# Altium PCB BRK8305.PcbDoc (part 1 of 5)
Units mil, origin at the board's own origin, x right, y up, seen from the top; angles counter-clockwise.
Board outline 5944.89 x 4139.76 mil, 4 copper layers (L1-Top, L2-GND, L3-GND, L4-BOT), stack 61.2 mil thick; 237 components, 286 nets, 1257 pads, 698 vias.
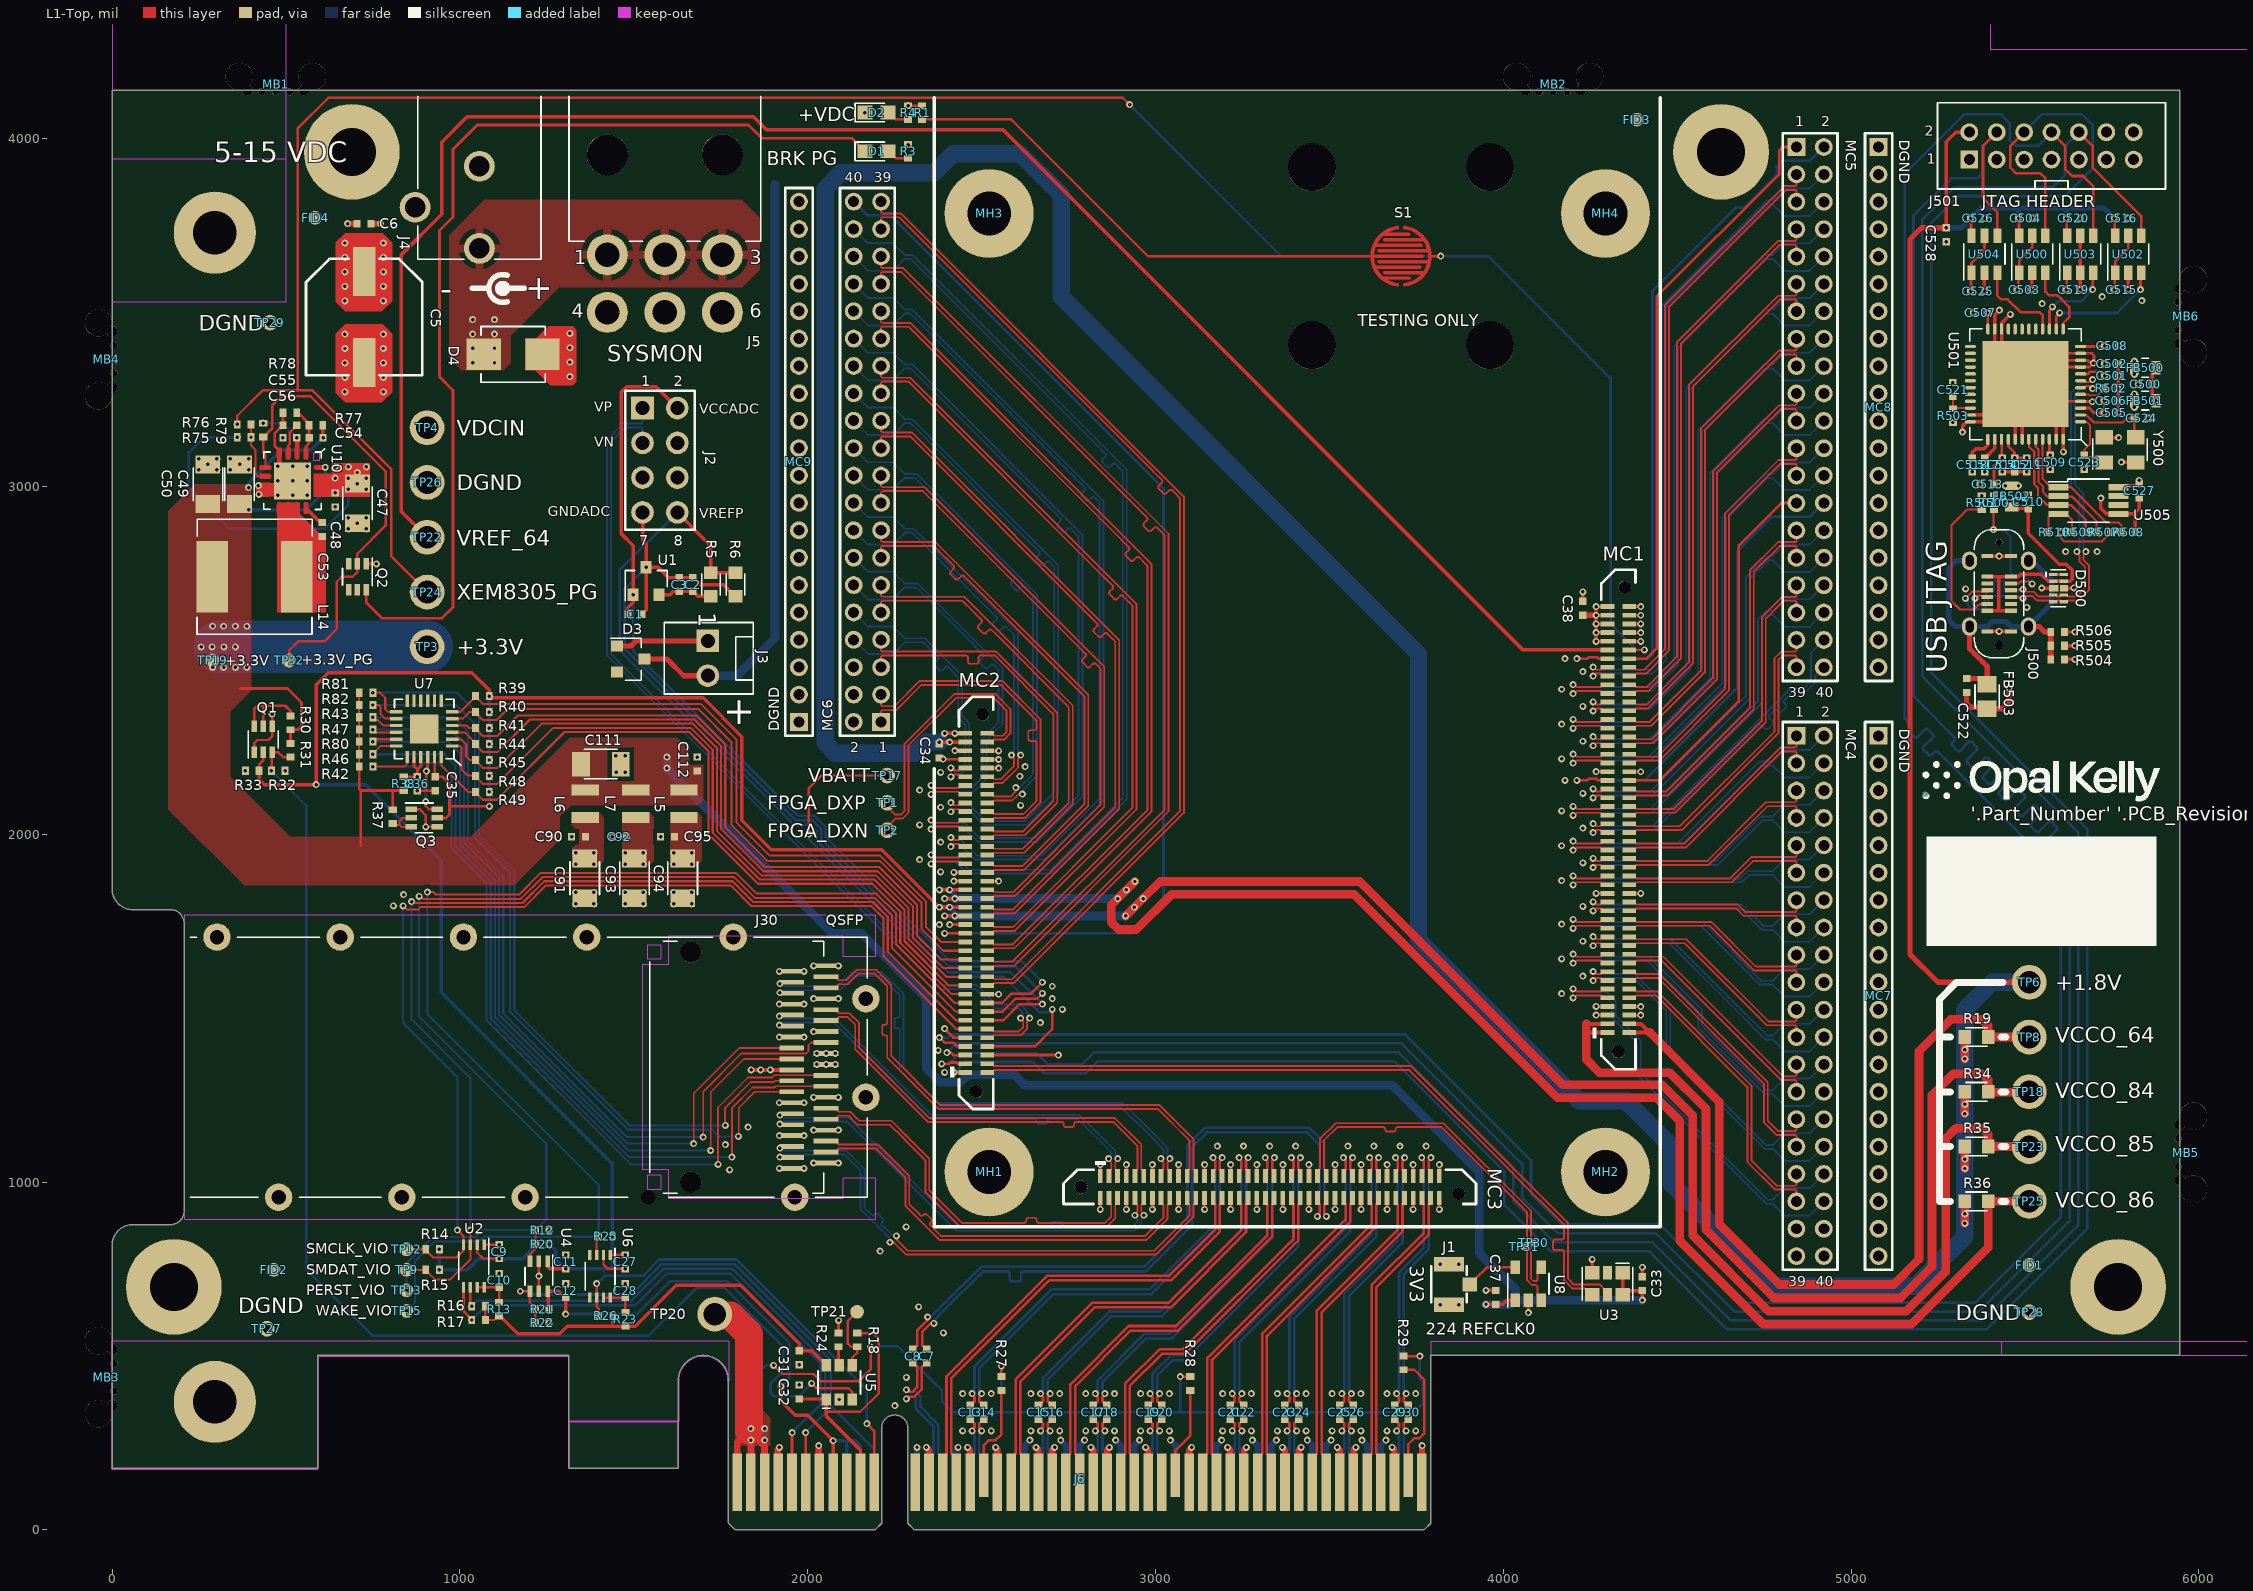
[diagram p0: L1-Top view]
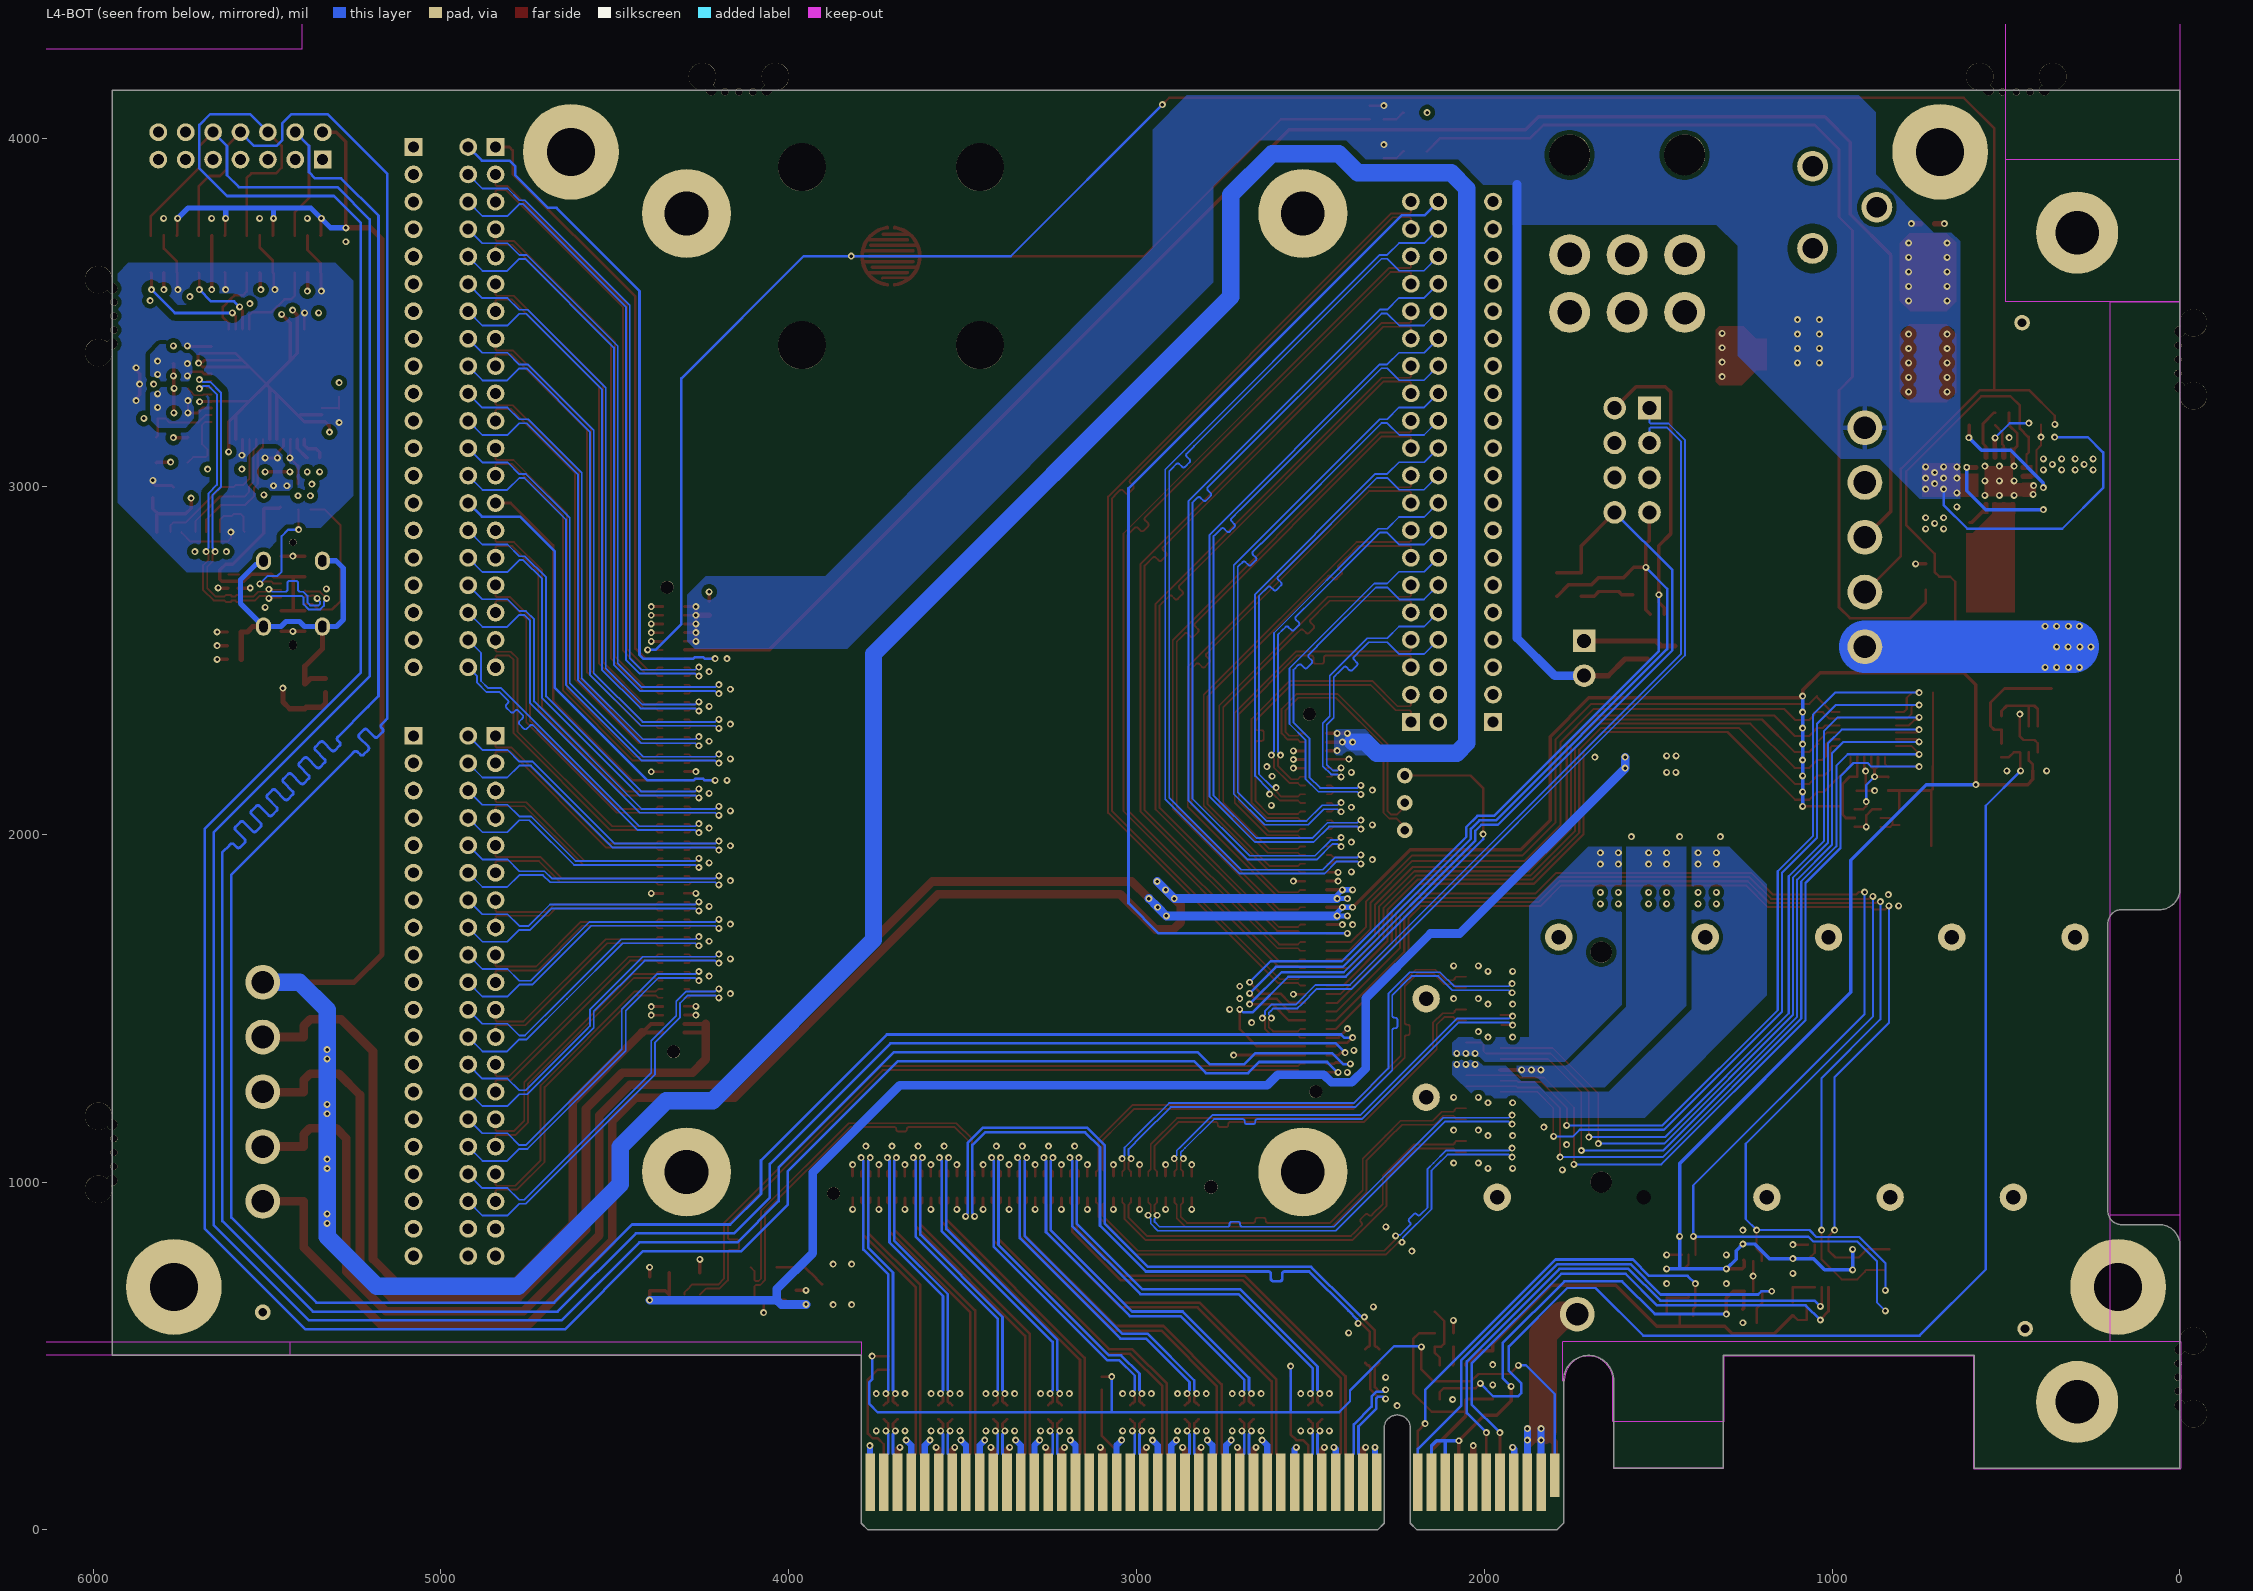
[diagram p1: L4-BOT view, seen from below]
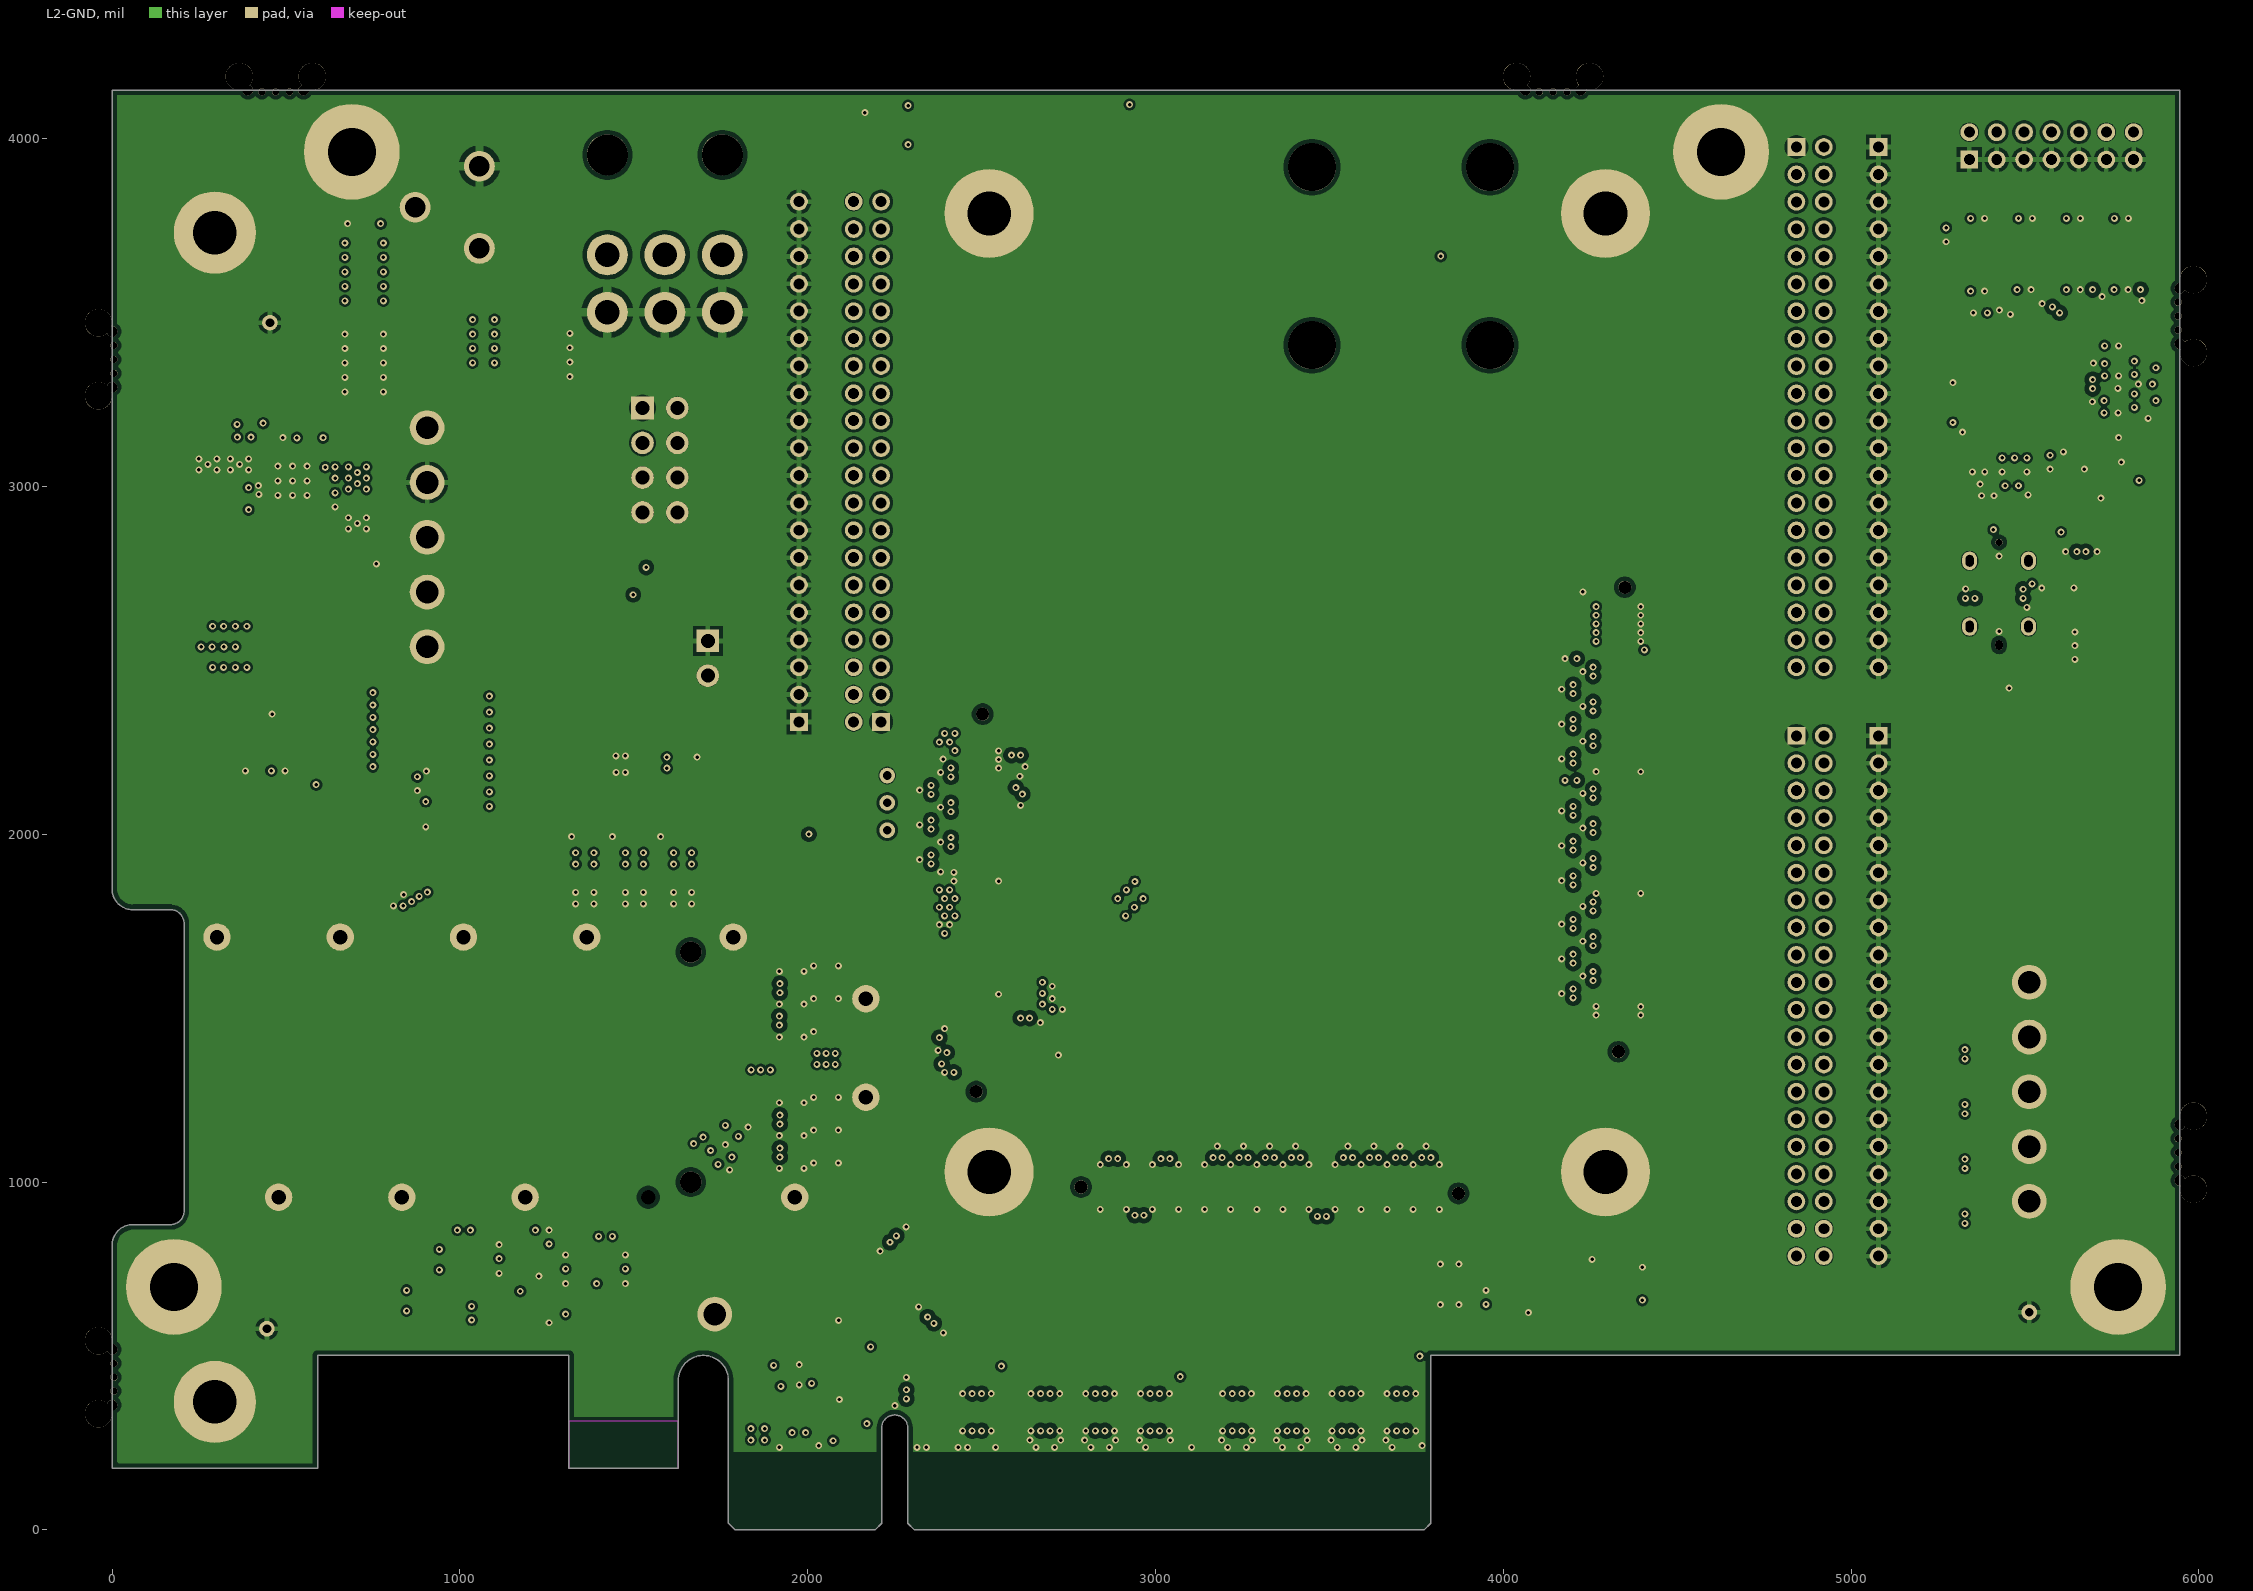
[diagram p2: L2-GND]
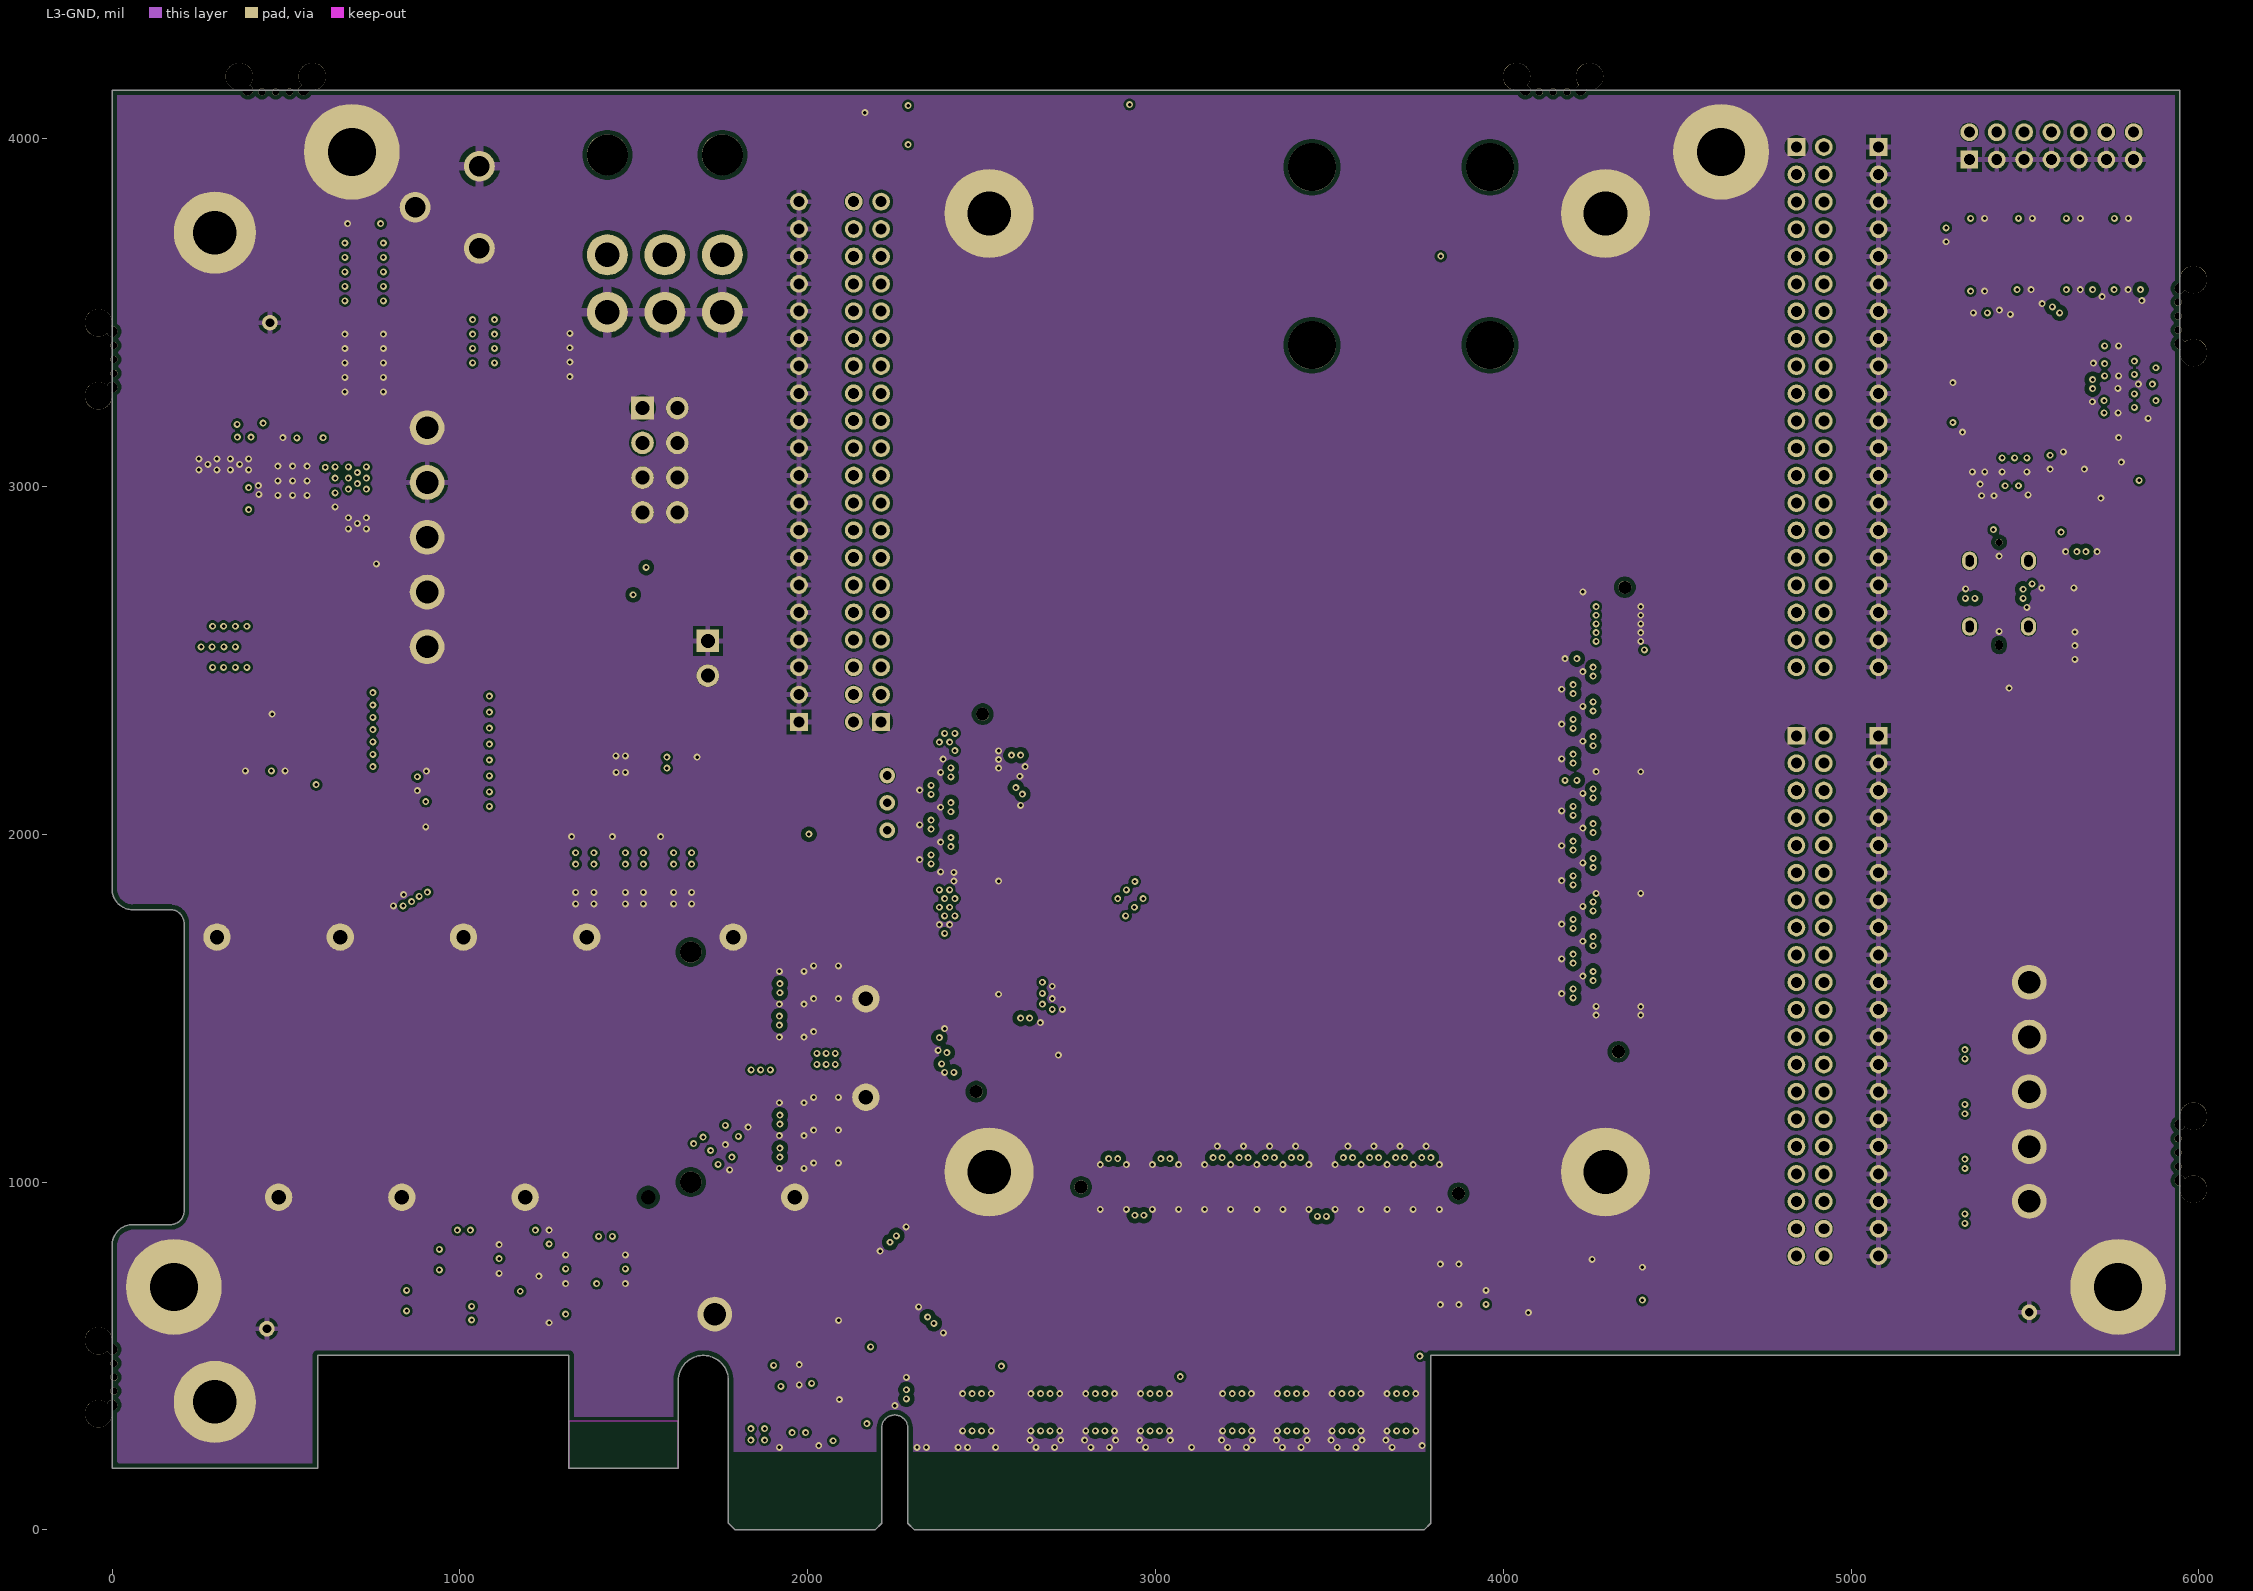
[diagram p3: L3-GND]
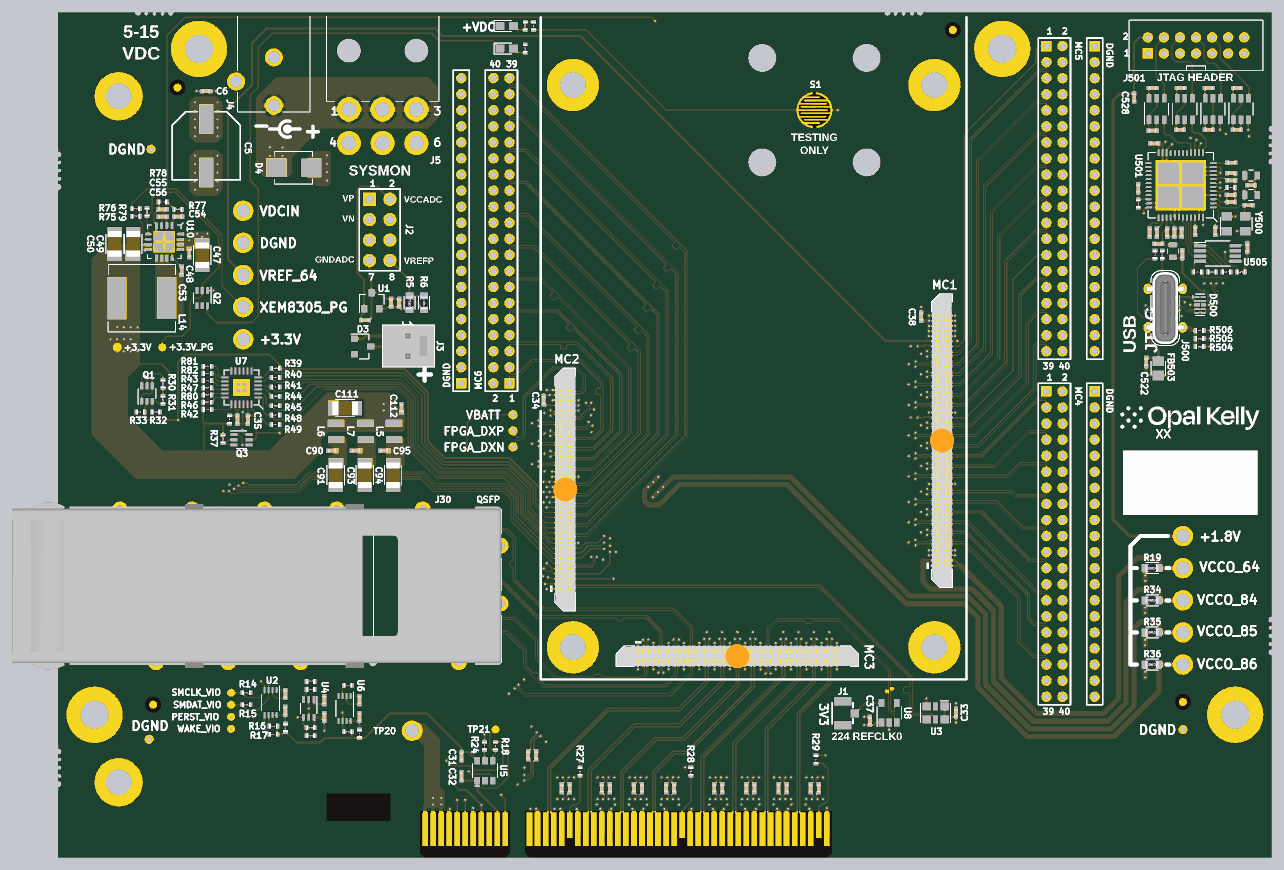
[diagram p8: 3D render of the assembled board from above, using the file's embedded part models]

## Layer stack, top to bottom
Top Solder: solder mask 0.4, Solder Resist, Dk 3.5
L1-Top: signal copper 1.4
Dielectric 2: prepreg 5.08, IT180A, Dk 4.2
L2-GND: signal copper 1.4
Dielectric 1: core 45.44, IT180A, Dk 4.2
L3-GND: signal copper 1.4
Dielectric 3: prepreg 5.08, IT180A, Dk 4.2
L4-BOT: signal copper 1.4
Solder Side: solder mask 0.4, Solder Resist, Dk 3.5

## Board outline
-0.01,177.16 590.54,177.16 590.54,501.97 1312.98,501.97 1312.98,177.16 1627.94,177.16 1627.94,430.12 cw(c1699.8,430.12) 1771.65,430.12 1771.65,19.68 1791.33,0 2192.91,0 2212.59,19.68 2212.59,293.31 cw(c2249.99,293.31) 2287.39,293.31 2287.39,19.68 2307.08,0 3771.65,0 3791.33,19.68 3791.33,501.97 5944.88,501.97 5944.88,4139.76 -0.01,4139.76 -0.01,1842.52 ccw(c59.05,1842.52) 59.06,1783.46 167.46,1783.46 cw(c167.46,1744.09) 206.83,1744.09 206.83,917.32 cw(c167.46,917.32) 167.46,877.95 59.06,877.95 ccw(c59.06,818.9) 0,818.9

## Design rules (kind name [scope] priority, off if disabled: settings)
BoardOutlineClearance [not (HasFootprint('PCIEx8-FULL-HEIGHT') or Name Like 'MB*')] p1: gap=15 ignorepadtopadclearanceinfootprint=FALSE
Clearance Clearance_50ohmSpace [InNetClass('50ohm') and not (TouchesRoom('JTAG-MC') or TouchesRoom('FTDI')) vs InNetClass('50ohm')] p1: gap=6 ignorepadtopadclearanceinfootprint=FALSE except(7.5: Track-Hole; 18: Arc-Track Arc-Fill Arc-Poly Track-Track Track-Fill Track-Poly SMDPad-Fill SMDPad-Poly THPad-Fill THPad-Poly Via-Fill Via-Poly Fill-Fill Fill-Poly Poly-Poly)
Clearance Clearance_50ohm [InNetClass('50ohm')] p2: gap=6 ignorepadtopadclearanceinfootprint=FALSE except(7.5: Track-Hole; 18: Arc-Fill Arc-Poly Track-Fill Track-Poly SMDPad-Fill SMDPad-Poly THPad-Fill THPad-Poly Via-Fill Via-Poly Fill-Fill Fill-Poly Poly-Poly)
Clearance Clearance_diffPairOverride [(InDifferentialPairClass('100ohm_Diff') or InDifferentialPairClass('85ohm_diff') or InDifferentialPairClass('90ohm_diff')) and (((TouchesRoom('MC1') or TouchesRoom('MC2') or TouchesRoom('M.2')) and OnTop) or ((TouchesRoom('MC4') or TouchesRoom('MC6') or TouchesRoom('MC7') or TouchesRoom('MC8')) and OnBottom))] p3: gap=6 ignorepadtopadclearanceinfootprint=FALSE except(7.5: Track-Hole; 12: Arc-Fill Arc-Poly Track-Fill Track-Poly SMDPad-Fill SMDPad-Poly THPad-Fill THPad-Poly Via-Fill Via-Poly Fill-Fill Fill-Poly Poly-Poly Poly-Region Region-Region)
Clearance Clearance_diffPairVia [(InDifferentialPairClass('100ohm_Diff') or InDifferentialPairClass('85ohm_diff') or InDifferentialPairClass('90ohm_diff')) and (IsVia or IsPad) and not (HasFootprint('SAMTEC_BDRA-92SJP-02-12-0100') or HasFootprint('D5V0FS4U10LP'))] p4: gap=6 ignorepadtopadclearanceinfootprint=FALSE except(18: Arc-Fill Arc-Poly Arc-Region Track-Fill Track-Poly Track-Region SMDPad-Fill SMDPad-Poly SMDPad-Region THPad-Fill THPad-Poly THPad-Region Via-Fill Via-Poly Via-Region Fill-Fill Fill-Poly Fill-Region Poly-Poly Poly-Region Region-Region)
Clearance Clearance_diffPair [(InDifferentialPairClass('100ohm_Diff') or InDifferentialPairClass('85ohm_diff') or InDifferentialPairClass('90ohm_diff')) and not (HasFootprint('SAMTEC_BDRA-92SJP-02-12-0100') or HasFootprint('D5V0FS4U10LP'))] p5: gap=18 ignorepadtopadclearanceinfootprint=FALSE
Clearance Clearance_MouseBite [(Name Like 'MB*') vs (Name Like 'MB*')] p6: gap=15 ignorepadtopadclearanceinfootprint=FALSE
Clearance [All] p7: gap=5.75 ignorepadtopadclearanceinfootprint=FALSE except(7.5: Track-Hole; 12: Arc-Fill Arc-Poly Track-Fill Track-Poly SMDPad-Fill SMDPad-Poly THPad-Fill THPad-Poly Via-Fill Via-Poly Fill-Fill Fill-Poly Poly-Poly Poly-Region Region-Region)
DiffPairsRouting 100ohm_diff [InDifferentialPairClass('100ohm_Diff')] p1: maxlimit=6 minlimit=1 mostfreqgap=6 toplayer_mingap=6 toplayer_minwidth=5.25 toplayer_maxwidth=5.25 toplayer_prefwidth=5.25 midlayer1_maxgap=1 midlayer1_prefgap=1 midlayer1_minwidth=1 midlayer1_maxwidth=1 midlayer1_prefwidth=1 midlayer2_maxgap=1 midlayer2_prefgap=1 midlayer2_minwidth=1 midlayer2_maxwidth=1 midlayer2_prefwidth=1 bottomlayer_mingap=6 bottomlayer_minwidth=5.25 bottomlayer_maxwidth=5.25 bottomlayer_prefwidth=5.25 maxuncoupledlength=500
DiffPairsRouting 90ohm_diff [InDifferentialPairClass('90ohm_diff')] p2: maxlimit=6 minlimit=1 mostfreqgap=6 toplayer_mingap=6 toplayer_minwidth=5.6 toplayer_maxwidth=5.6 toplayer_prefwidth=5.6 midlayer1_maxgap=1 midlayer1_prefgap=1 midlayer1_minwidth=1 midlayer1_maxwidth=1 midlayer1_prefwidth=1 midlayer2_maxgap=1 midlayer2_prefgap=1 midlayer2_minwidth=1 midlayer2_maxwidth=1 midlayer2_prefwidth=1 bottomlayer_mingap=6 bottomlayer_minwidth=5.6 bottomlayer_maxwidth=5.6 bottomlayer_prefwidth=5.6 maxuncoupledlength=500
DiffPairsRouting 85ohm_diff [InDifferentialPairClass('85ohm_diff')] p3: maxlimit=6 minlimit=1 mostfreqgap=6 toplayer_mingap=6 toplayer_minwidth=7.5 toplayer_maxwidth=7.5 toplayer_prefwidth=7.5 midlayer1_maxgap=1 midlayer1_prefgap=1 midlayer1_minwidth=1 midlayer1_maxwidth=1 midlayer1_prefwidth=1 midlayer2_maxgap=1 midlayer2_prefgap=1 midlayer2_minwidth=1 midlayer2_maxwidth=1 midlayer2_prefwidth=1 bottomlayer_mingap=6 bottomlayer_minwidth=7.5 bottomlayer_maxwidth=7.5 bottomlayer_prefwidth=7.5 maxuncoupledlength=500
DiffPairsRouting DiffPairsRouting_NotSet [All] p4: maxlimit=10 minlimit=10 mostfreqgap=10 toplayer_minwidth=15 toplayer_maxwidth=15 toplayer_prefwidth=15 midlayer1_minwidth=15 midlayer1_maxwidth=15 midlayer1_prefwidth=15 midlayer2_minwidth=15 midlayer2_maxwidth=15 midlayer2_prefwidth=15 bottomlayer_minwidth=15 bottomlayer_maxwidth=15 bottomlayer_prefwidth=15 maxuncoupledlength=500
FabricationTestPointUsage TestPointUsage [All] p1: valid=0 allowmultiple=FALSE
FabricationTestpoint Testpoint [All] p1: side=3 testpointundercomponent=TRUE minsize=40 maxsize=100 preferedsize=60 minholesize=0 maxholesize=40 preferedholesize=32 testpointgrid=1 allowsidetop=TRUE allowsidebottom=TRUE usegrid=TRUE gridtolerance=0.01
HoleSize [All] p1: absolutevalues=TRUE maxlimit=250 minlimit=8 maxpercent=80.000 minpercent=20.000
HoleToHoleClearance [not (Name Like 'MB*')] p1: gap=10 allowstackedmicrovias=TRUE
MatchedLengths MatchedLengths_JTAG [InxSignalClass('JTAG')] p1: tolerance=10 checknetsindiffpair=FALSE checkdiffpairvsdiffpair=TRUE checkxsignals=TRUE checkothers=TRUE
MatchedLengths [InxSignalClass('All xSignals')] p2: tolerance=5 checknetsindiffpair=TRUE checkdiffpairvsdiffpair=FALSE checkxsignals=FALSE checkothers=FALSE
MinimumAnnularRing [All] p1: minimumring=5
MinimumSolderMaskSliver [All] p1: minsoldermaskwidth=2
PlaneConnect [All] p1: planeconnectstyle=Direct reliefexpansion=20 reliefentries=4 reliefconductorwidth=10 reliefairgap=10
PolygonConnect "Via Connect" [IsVia] p1: connectstyle=Direct reliefconductorwidth=10 reliefentries=4 polygonreliefangle="90 Angle" airgapwidth=10
PolygonConnect PolygonPowerConnect [HasFootprint('SAMTEC_BDRA-92SJP-02-12-0100') or HasFootprint('CUI-PJ102A') or HasFootprint('0455580003')] p2: connectstyle=Relief reliefconductorwidth=25 reliefentries=4 polygonreliefangle="90 Angle" airgapwidth=15
PolygonConnect PolygonConnectGND [InNet('DGND')] p3: connectstyle=Relief reliefconductorwidth=15 reliefentries=4 polygonreliefangle="90 Angle" airgapwidth=10
PolygonConnect [All] p4: thpad.connectstyle=Relief thpad.reliefconductorwidth=15 thpad.reliefentries=4 thpad.polygonreliefangle="90 Angle" thpad.airgapwidth=12 smdpad.connectstyle=Direct smdpad.reliefconductorwidth=20 smdpad.reliefentries=4 smdpad.polygonreliefangle="90 Angle" smdpad.airgapwidth=12 via.connectstyle=Direct via.reliefconductorwidth=20 via.reliefentries=4 via.polygonreliefangle="90 Angle" via.airgapwidth=12
ReturnPath ReturnPath_Diff [(InDifferentialPairClass('100ohm_Diff') or InDifferentialPairClass('85ohm_diff')) and (not ((TouchesRoom('MC1') or TouchesRoom('MC2') or TouchesRoom('M.2')) and OnTop) and (not (TouchesRoom('MC4') or TouchesRoom('MC6') or TouchesRoom('MC7') or TouchesRoom('MC8')) and OnBottom)) and not TouchesRoom('PCIE')] p1: impedanceprofileid={FC3A9359-EA79-4C24-837F-E158A8B04174} _gaplimit=0 _useantipads=TRUE
ReturnPath ReturnPath_SE [InNetClass('50ohm') and (not ((TouchesRoom('MC1') or TouchesRoom('MC2') or TouchesRoom('M.2') or TouchesRoom('JTAG') or TouchesRoom('PERST')) and OnTop) and not ((TouchesRoom('MC4') or TouchesRoom('MC6') or TouchesRoom('MC7') or TouchesRoom('MC8')) and OnBottom))] p2: impedanceprofileid={70E1A7AF-9659-420A-8032-69FB668B1DC2} _gaplimit=0 _useantipads=TRUE
RoomDefinition FTDI [False vs False] p1: confinementstyle=ConfineIn formatcopy=TRUE lockcomponents=FALSE outline 5534.14,3540.15 5636.58,3540.15 5636.58,3443.07 5534.14,3443.07
RoomDefinition JTAG-MC [False vs False] p2: confinementstyle=ConfineIn formatcopy=TRUE lockcomponents=FALSE outline 2354.33,1455.75 2496.06,1455.75 2496.06,1291.38 2354.33,1291.38
RoomDefinition PCIE [False] p3: confinementstyle=ConfineIn formatcopy=TRUE lockcomponents=FALSE outline 1761.41,228.35 3791.33,228.35 3791.33,-1.94 1761.41,-1.94
RoutingLayers [All] p1: top layer_v5=TRUE mid layer 1_v5=TRUE mid layer 2_v5=FALSE bottom layer_v5=TRUE
RoutingVias [All] p1: holewidth=10 width=20 viastyle="Through Hole" minholewidth=10 minwidth=20 maxholewidth=50 maxwidth=100
SilkToSilkClearance [All] p1: silktosilkclearance=0.1
SilkToSolderMaskClearance SilkscreenOverComponentPads [IsPad] p1: minsilkscreentomaskgap=2 clearancetoexposedcopper=TRUE
SolderMaskExpansion [All] p1: expansion=2 istentingtop=FALSE
ViasUnderSMD [All] p1: allowed=TRUE
Width Width_50ohm [InNetClass('50ohm')] p1: maxlimit=7.5 minlimit=7.5 preferedwidth=7.5 minimp=50.000000 maximp=50.000000 favimp=50.000000
Width okWidth [All] p2: maxlimit=150 minlimit=5 preferedwidth=8 minimp=50.000000 maximp=50.000000 favimp=50.000000
20 further rules are at their usual default settings.

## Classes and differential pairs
differential pair class 90ohm_diff: DP_USB_D
component class JTAG: C500 C501 C502 C503 C504 C505 C506 C507 C508 C509 C510 C511 C512 C513 C514 C515 C516 C517 C518 C519 C520 C521 C522 C523 C524 C525 C526 C527 C528 D500 FB500 FB501 FB502 FB503 J500 J501 R500 R501 R502 R503 R504 R505 R506 R507 R508 R509 R510 U500 U501 U502 U503 U504 U505 Y500
component class QSFP: C35 C36 C90 C91 C92 C93 C94 C95 C111 C112 J30 L5 L6 L7 Q3 QSFP R37 R38 R39 R40 R41 R42 R43 R44 R45 R46 R47 R48 R49 R80 R81 R82 U7
net class okPwr: +1.8V +3.3V +3.3V_PCIE_C +3.3VAUX_PCIE +3.3VAUX_PCIE_C +12V_PCIE_C +VDCIN
net class 50ohm: B64_T1U_N12 B64_T2U_N12 B64_T3U_N12 FPGA_JTAG_TCK FPGA_JTAG_TDI FPGA_JTAG_TDO FPGA_JTAG_TMS FTDI_TCK FTDI_TDI FTDI_TDO FTDI_TMS MGT_REFCLK0_224 RESERVED1
differential pair class 85ohm_diff: DP_MGT_REFCLK0_225_C DP_MGT_REFCLK1_225_C DP_MGT_RX0_224 DP_MGT_RX0_225 DP_MGT_RX1_224 DP_MGT_RX1_225 DP_MGT_RX2_224 DP_MGT_RX2_225 DP_MGT_RX3_224 DP_MGT_RX3_225 DP_MGT_TX0_224 DP_MGT_TX0_225 DP_MGT_TX1_224 DP_MGT_TX1_225 DP_MGT_TX2_224 DP_MGT_TX2_225 DP_MGT_TX3_224 DP_MGT_TX3_225 DP_PCIE_REFCLK_C DP_PCIE_RX0 DP_PCIE_RX1 DP_PCIE_RX2 DP_PCIE_RX3 DP_PCIE_RX4 DP_PCIE_RX5 DP_PCIE_RX6 DP_PCIE_RX7 DP_USB_D
component class "PCIE X8": C7 C8 C9 C10 C11 C12 C13 C14 C15 C16 C17 C18 C19 C20 C21 C22 C23 C24 C25 C26 C27 C28 C29 C30 C31 C32 J6 Q1 R12 R13 R14 R15 R16 R17 R18 R20 R21 R22 R23 R24 R25 R26 R27 R28 R29 R30 R31 R32 R33 TP9 TP12 TP13 TP15 TP20 TP21 U2 U4 U5 U6
component class BRK8305: * ASSY1 C1 C2 C3 C5 C6 C33 C34 C37 C38 C47 C48 C49 C50 C53 C54 C55 C56 D1 D2 D3 D4 FID1 FID2 FID3 FID4 J1 J2 J3 J4 J5 L14 LABEL1 MB1 MB2 MB3 MB4 MB5 MB6 MC1 MC2 MC3 MC4 MC5 MC6 MC7 MC8 MC9 MH1 MH2 MH3 MH4 PCB1 Q2 R1 R3 R4 R5 R6 R19 R34 R35 R36 R75 R76 R77 R78 R79 S1 TP1 TP2 TP3 TP4 TP6 TP8 TP17 TP18 TP19 TP22 TP23 TP24 TP25 TP26 TP27 TP28 TP29 TP30 TP31 TP32 U1 U3 U8 U10
differential pair class 100ohm_diff: DP_100MHZ_OSC_ DP_B64_L1 DP_B64_L2 DP_B64_L3 DP_B64_L4 DP_B64_L5 DP_B64_L6 DP_B64_L7 DP_B64_L8 DP_B64_L9 DP_B64_L10 DP_B64_L11_GC DP_B64_L12_GC DP_B64_L13_GC DP_B64_L14_GC DP_B64_L15 DP_B64_L16 DP_B64_L17 DP_B64_L18 DP_B64_L19 DP_B64_L20 DP_B64_L21 DP_B64_L22 DP_B64_L23 DP_B64_L24 DP_B67_L13_GC DP_B67_L14_GC DP_B67_L15 DP_B67_L16 DP_B67_L17 DP_B67_L18 DP_B67_L19 DP_B67_L20 DP_B67_L21 DP_B67_L22 DP_B67_L23 DP_B67_L24 DP_B84_L1 DP_B84_L2 DP_B84_L3 DP_B84_L4 DP_B84_L5_HDGC DP_B84_L6_HDGC DP_B84_L7_HDGC DP_B84_L8_HDGC DP_B84_L9 DP_B84_L10 DP_B84_L11 DP_B84_L12 DP_B85_L7_HDGC DP_B85_L8_HDGC DP_B85_L9 DP_B85_L10 DP_B85_L11 DP_B85_L12 DP_B86_L1 DP_B86_L2 DP_B86_L3 DP_B86_L4 DP_B86_L5_HDGC DP_B86_L6_HDGC DP_B86_L7_HDGC DP_B86_L8_HDGC DP_B86_L9 DP_B86_L10 DP_B86_L11 DP_B86_L12 DP_B87_L1 DP_B87_L2 DP_B87_L3 DP_B87_L4 DP_B87_L5_HDGC DP_B87_L6_HDGC DP_B87_L7_HDGC DP_B87_L8_HDGC DP_B87_L9 DP_B87_L10 DP_B87_L11 DP_B87_L12 DP_DX DP_MGT_REFCLK0_224_C DP_MGT_REFCLK0_226_C DP_MGT_RX0_226 DP_MGT_RX1_226 DP_MGT_RX2_226 DP_MGT_RX3_226 DP_MGT_TX0_226 DP_MGT_TX1_226 DP_MGT_TX2_226 DP_MGT_TX3_226 DP_XADC_V DP_XADC_V_C
differential pair DP_USB_D: +USB_DP -USB_DN
differential pair DP_DX: +FPGA_DXN -FPGA_DXP
differential pair DP_B85_L10: +B85_L10P -B85_L10N
differential pair DP_B85_L7_HDGC: +B85_L7P_HDGC -B85_L7N_HDGC
differential pair DP_B85_L8_HDGC: +B85_L8P_HDGC -B85_L8N_HDGC
differential pair DP_B85_L9: +B85_L9P -B85_L9N
differential pair DP_B85_L11: +B85_L11P -B85_L11N
differential pair DP_B85_L12: +B85_L12P -B85_L12N
differential pair DP_B84_L3: +B84_L3P -B84_L3N
differential pair DP_B64_L16: +B64_L16P -B64_L16N
differential pair DP_MGT_REFCLK0_225_C: +MGT_REFCLK0P_225_C -MGT_REFCLK0N_225_C
differential pair DP_XADC_V: +XADC_VP_C -XADC_VN_C
differential pair DP_PCIE_RX4: +PCIE_RX4P_C -PCIE_RX4N_C
differential pair DP_PCIE_RX5: +PCIE_RX5P_C -PCIE_RX5N_C
differential pair DP_PCIE_RX6: +PCIE_RX6P_C -PCIE_RX6N_C
differential pair DP_PCIE_RX7: +PCIE_RX7P_C -PCIE_RX7N_C
differential pair DP_PCIE_RX0: +PCIE_RX0P_C -PCIE_RX0N_C
differential pair DP_PCIE_RX1: +PCIE_RX1P_C -PCIE_RX1N_C
differential pair DP_PCIE_RX2: +PCIE_RX2P_C -PCIE_RX2N_C
differential pair DP_PCIE_RX3: +PCIE_RX3P_C -PCIE_RX3N_C
differential pair DP_PCIE_REFCLK_C: +PCIE_REFCLKP_C -PCIE_REFCLKN_C
differential pair DP_MGT_REFCLK0_226_C: +MGT_REFCLK0P_226_C -MGT_REFCLK0N_226_C
differential pair DP_MGT_REFCLK1_225_C: +"" -""
differential pair DP_MGT_RX0_224: +MGT_RXP0_224 -MGT_RXN0_224
differential pair DP_MGT_RX0_225: +MGT_RXP0_225 -MGT_RXN0_225
differential pair DP_MGT_RX0_226: +MGT_RXP0_226 -MGT_RXN0_226
differential pair DP_MGT_RX1_224: +MGT_RXP1_224 -MGT_RXN1_224
differential pair DP_MGT_RX1_225: +MGT_RXP1_225 -MGT_RXN1_225
differential pair DP_MGT_RX1_226: +MGT_RXP1_226 -MGT_RXN1_226
differential pair DP_MGT_RX2_224: +MGT_RXP2_224 -MGT_RXN2_224
differential pair DP_MGT_RX2_225: +MGT_RXP2_225 -MGT_RXN2_225
differential pair DP_MGT_RX2_226: +MGT_RXP2_226 -MGT_RXN2_226
differential pair DP_MGT_RX3_224: +MGT_RXP3_224 -MGT_RXN3_224
differential pair DP_MGT_RX3_225: +MGT_RXP3_225 -MGT_RXN3_225
differential pair DP_MGT_RX3_226: +MGT_RXP3_226 -MGT_RXN3_226
differential pair DP_MGT_TX0_224: +MGT_TXP0_224 -MGT_TXN0_224
differential pair DP_MGT_TX0_225: +MGT_TXP0_225 -MGT_TXN0_225
differential pair DP_MGT_TX0_226: +MGT_TXP0_226 -MGT_TXN0_226
differential pair DP_MGT_TX1_224: +MGT_TXP1_224 -MGT_TXN1_224
differential pair DP_MGT_TX1_225: +MGT_TXP1_225 -MGT_TXN1_225
differential pair DP_MGT_TX1_226: +MGT_TXP1_226 -MGT_TXN1_226
differential pair DP_MGT_TX2_224: +MGT_TXP2_224 -MGT_TXN2_224
differential pair DP_MGT_TX2_225: +MGT_TXP2_225 -MGT_TXN2_225
differential pair DP_MGT_TX2_226: +MGT_TXP2_226 -MGT_TXN2_226
differential pair DP_MGT_TX3_224: +MGT_TXP3_224 -MGT_TXN3_224
differential pair DP_MGT_TX3_225: +MGT_TXP3_225 -MGT_TXN3_225
differential pair DP_MGT_TX3_226: +MGT_TXP3_226 -MGT_TXN3_226
differential pair DP_XADC_V_C: +XADC_VP_C -XADC_VN_C
differential pair DP_MGT_REFCLK0_224_C: +MGT_REFCLK0P_224_C -MGT_REFCLK0N_224_C
differential pair DP_100MHZ_OSC_: +"" -""
differential pair DP_B64_L1: +B64_L1P -B64_L1N
differential pair DP_B64_L2: +B64_L2P -B64_L2N
differential pair DP_B64_L3: +B64_L3P -B64_L3N
differential pair DP_B64_L4: +B64_L4P -B64_L4N
differential pair DP_B64_L5: +B64_L5P -B64_L5N
differential pair DP_B64_L6: +B64_L6P -B64_L6N
differential pair DP_B64_L7: +B64_L7P -B64_L7N
differential pair DP_B64_L8: +B64_L8P -B64_L8N
differential pair DP_B64_L9: +B64_L9P -B64_L9N
differential pair DP_B64_L10: +B64_L10P -B64_L10N
differential pair DP_B64_L11_GC: +B64_L11P_GC -B64_L11N_GC
differential pair DP_B64_L12_GC: +B64_L12P_GC -B64_L12N_GC
differential pair DP_B64_L13_GC: +B64_L13P_GC -B64_L13N_GC
differential pair DP_B64_L14_GC: +B64_L14P_GC -B64_L14N_GC
differential pair DP_B64_L15: +B64_L15P -B64_L15N
differential pair DP_B64_L17: +B64_L17P -B64_L17N
differential pair DP_B64_L18: +B64_L18P -B64_L18N
differential pair DP_B64_L19: +B64_L19P -B64_L19N
differential pair DP_B64_L20: +B64_L20P -B64_L20N
differential pair DP_B64_L21: +B64_L21P -B64_L21N
differential pair DP_B64_L22: +B64_L22P -B64_L22N
differential pair DP_B64_L23: +B64_L23P -B64_L23N
differential pair DP_B64_L24: +B64_L24P -B64_L24N
differential pair DP_B67_L13_GC: +"" -""
differential pair DP_B67_L14_GC: +"" -""
differential pair DP_B67_L15: +"" -""
differential pair DP_B67_L16: +"" -""
differential pair DP_B67_L17: +"" -""
differential pair DP_B67_L18: +"" -""
differential pair DP_B67_L19: +"" -""
differential pair DP_B67_L20: +"" -""
differential pair DP_B67_L21: +"" -""
differential pair DP_B67_L22: +"" -""
differential pair DP_B67_L23: +"" -""
differential pair DP_B67_L24: +"" -""
differential pair DP_B84_L1: +B84_L1P -B84_L1N
differential pair DP_B84_L2: +B84_L2P -B84_L2N
differential pair DP_B84_L4: +B84_L4P -B84_L4N
differential pair DP_B84_L5_HDGC: +B84_L5P_HDGC -B84_L5N_HDGC
differential pair DP_B84_L6_HDGC: +B84_L6P_HDGC -B84_L6N_HDGC
differential pair DP_B84_L7_HDGC: +B84_L7P_HDGC -B84_L7N_HDGC
differential pair DP_B84_L8_HDGC: +B84_L8P_HDGC -B84_L8N_HDGC
differential pair DP_B84_L9: +B84_L9P -B84_L9N
differential pair DP_B84_L10: +B84_L10P -B84_L10N
differential pair DP_B84_L11: +B84_L11P -B84_L11N
differential pair DP_B84_L12: +B84_L12P -B84_L12N
differential pair DP_B86_L1: +B86_L1P -B86_L1N
differential pair DP_B86_L2: +B86_L2P -B86_L2N
differential pair DP_B86_L3: +B86_L3P -B86_L3N
differential pair DP_B86_L4: +B86_L4P -B86_L4N
differential pair DP_B86_L5_HDGC: +B86_L5P_HDGC -B86_L5N_HDGC
differential pair DP_B86_L6_HDGC: +B86_L6P_HDGC -B86_L6N_HDGC
differential pair DP_B86_L7_HDGC: +B86_L7P_HDGC -B86_L7N_HDGC
differential pair DP_B86_L8_HDGC: +B86_L8P_HDGC -B86_L8N_HDGC
differential pair DP_B86_L9: +B86_L9P -B86_L9N
differential pair DP_B86_L10: +B86_L10P -B86_L10N
differential pair DP_B86_L11: +B86_L11P -B86_L11N
differential pair DP_B86_L12: +B86_L12P -B86_L12N
differential pair DP_B87_L1: +"" -""
differential pair DP_B87_L2: +"" -""
differential pair DP_B87_L3: +"" -""
differential pair DP_B87_L4: +"" -""
differential pair DP_B87_L5_HDGC: +"" -""
differential pair DP_B87_L6_HDGC: +"" -""
differential pair DP_B87_L7_HDGC: +"" -""
differential pair DP_B87_L8_HDGC: +"" -""
differential pair DP_B87_L9: +"" -""
differential pair DP_B87_L10: +"" -""
differential pair DP_B87_L11: +"" -""
differential pair DP_B87_L12: +"" -""

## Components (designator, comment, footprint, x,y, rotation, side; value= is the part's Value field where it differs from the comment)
* "Opal Kelly Logo" okLogo-23x5-2021 5214.76,2110.85 r0 top
C1 "C0402C104K8PACTU" CAPC1005X06A 1502.88,2632.55 r0 top value="0.1 u"
C2 "GRM155C80J106ME11D" CAPC1005X06A 1669.84,2718.43 r270 top value=10u
C3 "C0402C104K8PACTU" CAPC1005X06A 1630.62,2718.43 r90 top value="0.1 u"
C5 "EEE-FK1E221P" CAPAE9083X70N 724.46,3487.56 r270 top value=220u
C6 "TMK105BJ104KV-F" CAPC1005X06A 724.41,3755.91 r0 top value="0.1 u"
C7 "C0402C104K8PACTU" CAPC1005X06A 2341.62,500.15 r90 top value="0.1 u"
C8 "C0402C104K8PACTU" CAPC1005X06A 2302.25,500.15 r90 top value="0.1 u"
C9 "C0402C104K8PACTU" CAPC1005X06A 1112.49,800.62 r270 top value="0.1 u"
C10 "C0402C104K8PACTU" CAPC1005X06A 1112.49,717.94 r270 top value="0.1 u"
C11 "C0402C104K8PACTU" CAPC1005X06A 1303.43,770.7 r270 top value="0.1 u"
C12 "C0402C104K8PACTU" CAPC1005X06A 1303.43,688.02 r270 top value="0.1 u"
C13 "C0402C104K8PACTU" CAPC1005X06A 2466.53,338.58 r90 top value="0.1 u"
C14 "C0402C104K8PACTU" CAPC1005X06A 2505.9,338.58 r90 top value="0.1 u"
C15 "C0402C104K8PACTU" CAPC1005X06A 2663.38,338.58 r90 top value="0.1 u"
C16 "C0402C104K8PACTU" CAPC1005X06A 2702.75,338.58 r90 top value="0.1 u"
C17 "C0402C104K8PACTU" CAPC1005X06A 2820.86,338.58 r90 top value="0.1 u"
C18 "C0402C104K8PACTU" CAPC1005X06A 2860.23,338.58 r90 top value="0.1 u"
C19 "C0402C104K8PACTU" CAPC1005X06A 2978.34,338.58 r90 top value="0.1 u"
C20 "C0402C104K8PACTU" CAPC1005X06A 3017.71,338.58 r90 top value="0.1 u"
C21 "C0402C104K8PACTU" CAPC1005X06A 3214.56,338.58 r90 top value="0.1 u"
C22 "C0402C104K8PACTU" CAPC1005X06A 3253.93,338.58 r90 top value="0.1 u"
C23 "C0402C104K8PACTU" CAPC1005X06A 3372.04,338.58 r90 top value="0.1 u"
C24 "C0402C104K8PACTU" CAPC1005X06A 3411.41,338.58 r90 top value="0.1 u"
C25 "C0402C104K8PACTU" CAPC1005X06A 3529.52,338.58 r90 top value="0.1 u"
C26 "C0402C104K8PACTU" CAPC1005X06A 3568.89,338.58 r90 top value="0.1 u"
C27 "C0402C104K8PACTU" CAPC1005X06A 1475.67,770.7 r270 top value="0.1 u"
C28 "C0402C104K8PACTU" CAPC1005X06A 1475.67,688.02 r270 top value="0.1 u"
C29 "C0402C104K8PACTU" CAPC1005X06A 3687,338.58 r90 top value="0.1 u"
C30 "C0402C104K8PACTU" CAPC1005X06A 3726.37,338.58 r90 top value="0.1 u"
C31 "C0402C104K8PACTU" CAPC1005X06A 1975.47,495.16 r90 top value="0.1 u"
C32 "C0402C104K8PACTU" CAPC1005X06A 1975.47,397 r270 top value="0.1 u"
C33 "C0402C104K8PACTU" CAPC1005X06A 4399.38,708.19 r270 top value="0.1 u"
C34 "C0402C104K8PACTU" CAPC1005X06A 2378.07,2240.02 r90 top value="0.1 u"
C35 "SM-0402, 10%, 10v" CAPC1005X06A 928.74,2145.67 r90 top value="0.1 u"
C36 "SM-0402, 10%, 10v" CAPC1005X06A 877.46,2145.57 r90 top value="0.1 u"
C37 "SM-0402, 10%, 10v" CAPC1005X06A 3977.56,668.69 r270 top value="0.1 u"
C38 "TMK105BJ104KV-F" CAPC1005X06A 4228.45,2650.18 r270 top value="0.1 u"
C47 "C3216X5R1V226M160AC" CAPC3216N 705.15,2951.61 r90 top value="22 u"
C48 "TMK105BJ104KV-F" CAPC1005X06A 641.15,2961.61 r90 top value="0.1 u"
C49 "LMK316AB7226KL-TR" CAPC3216N 366.15,3006.61 r270 top value=22u
C50 "LMK316AB7226KL-TR" CAPC3216N 275.15,3006.61 r270 top value=22u
C53 "C0402C104K8PACTU" CAPC1005X06A 604.15,2876.69 r270 top value="0.1 u"
C54 "CBR04C100J5GAC" CAPC1005X06A 586.55,3140.61 r0 top value=10p
C55 "C0402C332K5RACTU" CAPC1005X06A 510.76,3176.22 r0 top value="3.3 n"
C56 "LMK105BJ105KV-F" CAPC1005X06A 510.76,3140.61 r0 top value=1u
C90 "SM-0402, 10%, 10v" CAPC1005X06A 1341.2,1993.4 r0 top value="0.1 u"
C91 "SM-1206, 10%, 10v, X7R" CAPC3216N 1358.71,1873.32 r90 top value=22u
C92 "SM-0402, 10%, 10v" CAPC1005X06A 1458.12,1993.4 r0 top value="0.1 u"
C93 "SM-1206, 10%, 10v, X7R" CAPC3216N 1501.43,1873.32 r90 top value=22u
C94 "SM-1206, 10%, 10v, X7R" CAPC3216N 1640.21,1873.32 r90 top value=22u
C95 "SM-0402, 10%, 10v" CAPC1005X06A 1596.9,1993.4 r0 top value="0.1 u"
C111 "SM-1206, 10%, 10v, X7R" CAPC3216N 1404.97,2202.06 r180 top value=22u
C112 "SM-0402, 10%, 10v" CAPC1005X06A 1681.54,2202.06 r270 top value="0.1 u"
C500 "JMK105BBJ475MV-F" CAPC1005X06A 5845.62,3294.49 r0 top value=4.7u
C501 "JMK105BBJ475MV-F" CAPC1005X06A 5748.77,3318.11 r180 top value=4.7u
C502 "C0402C104K8PACTU" CAPC1005X06A 5748.77,3353.55 r180 top value="0.1 u"
C503 "C0402C104K8PACTU" CAPC1005X06A 5497.2,3566.15 r180 top value="0.1 u"
C504 "C0402C104K8PACTU" CAPC1005X06A 5501.13,3770.87 r180 top value="0.1 u"
C505 "JMK105BBJ475MV-F" CAPC1005X06A 5747.2,3211.82 r180 top value=4.7u
C506 "C0402C104K8PACTU" CAPC1005X06A 5746.8,3247.25 r180 top value="0.1 u"
C507 "C0402C104K8PACTU" CAPC1005X06A 5371.21,3499.22 r0 top value="0.1 u"
C508 "C0402C104K8PACTU" CAPC1005X06A 5748.77,3404.73 r180 top value="0.1 u"
C509 "C0402C104K8PACTU" CAPC1005X06A 5572,3070.08 r90 top value="0.1 u"
C510 "C0402C103K4RACTU" CAPC1005X06A 5509.01,2955.91 r270 top value="0.01 u"
C511 "JMK105BBJ475MV-F" CAPC1005X06A 5505.07,3062.21 r90 top value=4.7u
C512 "C0402C104K8PACTU" CAPC1005X06A 5469.64,3062.21 r90 top value="0.1 u"
C513 "JMK105BBJ475MV-F" CAPC1005X06A 5390.9,3007.09 r0 top value=4.7u
C514 "C0402C104K8PACTU" CAPC1005X06A 5434.2,3062.21 r90 top value="0.1 u"
C515 "C0402C104K8PACTU" CAPC1005X06A 5776.33,3566.15 r180 top value="0.1 u"
C516 "C0402C104K8PACTU" CAPC1005X06A 5776.72,3770.87 r180 top value="0.1 u"
C517 "C0402C104K8PACTU" CAPC1005X06A 5384.01,3062.21 r90 top value="0.1 u"
C518 "C0402C104K8PACTU" CAPC1005X06A 5348.57,3062.21 r90 top value="0.1 u"
C519 "C0402C104K8PACTU" CAPC1005X06A 5638.53,3566.15 r180 top value="0.1 u"
C520 "C0402C104K8PACTU" CAPC1005X06A 5638.93,3770.87 r180 top value="0.1 u"
C521 "C0402C103K4RACTU" CAPC1005X06A 5292.47,3278.74 r270 top value="0.01 u"
C522 "SM-0402, 10%, 10v" CAPC1005X06A 5331.84,2428.35 r90 top value="0.1 u"
C523 "C0402C180J5GACTU" CAPC1005X06A 5670.42,3070.08 r90 top value="18 p"
C524 "C0402C180J5GACTU" CAPC1005X06A 5833.81,3196.07 r180 top value="18 p"
C525 "C0402C104K8PACTU" CAPC1005X06A 5363.34,3562.21 r180 top value="0.1 u"
C526 "C0402C104K8PACTU" CAPC1005X06A 5363.34,3770.87 r180 top value="0.1 u"
C527 "C0402C104K8PACTU" CAPC1005X06A 5827.9,2987.41 r90 top value="0.1 u"
C528 "SM-0402, 10%, 10v" CAPC1005X06A 5272.79,3724.02 r90 top value="0.1 u"
D1 "BRK PG" CD1608-0603-PIN1-CATHODE 2197.79,3963.8 r0 top
D2 "+VDC" CD1608-0603-PIN1-CATHODE 2197.79,4075.46 r0 top
D3 "MMBD4148SE-TP" SOT23-95P240X110 1491.07,2504.01 r270 top
D4 "D ESD" DO-214AA 1152.8,3380.02 r180 top
D500 "D5V0FS4U10LP-7" D5V0FS4U10LP 5595.62,2707.88 r270 top
FB500 "MI0603J601R-10" INDC1608X06N 5845.23,3341.74 r180 top value=600
FB501 "MI0603J601R-10" INDC1608X06N 5845.23,3247.25 r180 top value=600
FB502 "MI0603J601R-10" INDC1608X06N 5461.76,2971.66 r270 top value=600
FB503 "BLM21PG221SN1D" RESC2012N 5390.9,2396.85 r270 top value=220
FID1 "FIDUCIAL" FID1MM/2MM-SS 5511.81,761.81 r90 top
FID2 "FIDUCIAL" FID1MM/2MM-SS 464.57,748.03 r90 top
FID3 "FIDUCIAL" FID1MM/2MM-SS 4383.78,4055.12 r90 top
FID4 "FIDUCIAL" FID1MM/2MM-SS 583.63,3772.91 r90 top
J1 "RXP0" UFL-R-SMT-1 3843.53,706.09 r90 top
J2 "PRPC004DAAN-RC" HDR2X4 1524.88,3225.82 r270 top locked
J3 "0022232021" MOLEX-0022232021 1712.55,2506.3 r270 top
J4 "PJ-102AH" CUI-PJ102A 1055.94,4224.15 r180 top
J5 "0455580003" 0455580003 1588.95,3666.5 r0 top
J6 "PCIe x8 Card-Edge Connector" PCIEx8-FULL-HEIGHT 2249.99,0 r0 top locked
J30 "FS1-Z38-20Z6-60" QSFP28_RECEPTACLE_SFF-8679 1663.53,1661.46 r270 top locked
J500 "USB4120-03-C" USB4120-03-C 5425.15,2692.13 r270 top
J501 "87831-1420" XILINX-JTAG 5575.94,3979.53 r0 top
L5 "CIGT252010LM1R0MNE" CIGT252010 1644.14,2087.89 r270 top value=1u
L6 "CIGT252010LM1R0MNE" CIGT252010 1360.68,2087.89 r270 top value=1u
L7 "CIGT252010LM1R0MNE" CIGT252010 1505.36,2087.89 r270 top value=1u
L14 "1267AY-3R3N=P3" 1267AY 409.16,2740.6 r180 top value=3.3u
MB1 "PCB Array Mouse Bite" MouseBite-01 470.33,4139.76 r0 top
MB2 "PCB Array Mouse Bite" MouseBite-01 4142.99,4139.76 r0 top
MB3 "PCB Array Mouse Bite" MouseBite-01 -0.01,439.25 r90 top
MB4 "PCB Array Mouse Bite" MouseBite-01 -0.01,3365.79 r90 top
MB5 "PCB Array Mouse Bite" MouseBite-01 5944.88,1084.97 r270 top
MB6 "PCB Array Mouse Bite" MouseBite-01 5944.88,3490.15 r270 top
MC1 "ERF6-50-03.5-L-DV-A-K-TR" ERF6-50-03.5-L-DV-A-K-TR 4330.71,2042.8 r270 top locked
MC2 "ERF6-40-03.5-L-DV-A-K-TR" ERF6-40-03.5-L-DV-A-K-TR 2484.25,1803.05 r270 top locked
MC3 "ERF6-40-03.5-L-DV-A-K-TR" ERF6-40-03.5-L-DV-A-K-TR 3328.25,986.22 r180 top locked
MC4 "0877584016" HDR2X20-2MM 4881.89,1535.43 r270 top
MC5 "0877584016" HDR2X20-2MM 4881.89,3228.35 r270 top
MC6 "0877584016" HDR2X20-2MM 2171.45,3071.26 r90 top
MC7 "Header, 20-Pin, Single Row" HDR1X20-2MM 5078.74,1535.43 r270 top
MC8 "Header, 20-Pin, Single Row" HDR1X20-2MM 5078.74,3228.35 r270 top
MC9 "Header, 20-Pin, Single Row" HDR1X20-2MM 1974.6,3071.26 r90 top
MH1 "MTG" MTG-3.2/6.5-PTH 2521.65,1029.53 r270 top locked
MH2 "MTG" MTG-3.2/6.5-PTH 4293.31,1029.53 r270 top locked
MH3 "MTG" MTG-3.2/6.5-PTH 2521.65,3785.43 r270 top locked
MH4 "MTG" MTG-3.2/6.5-PTH 4293.31,3785.43 r270 top locked
Q1 "SI1922EDH-T1-GE3" SOT363-6N 434.15,2273.29 r90 top
Q2 "SI1922EDH-T1-GE3" SOT363-6N 705.15,2740.6 r270 top
Q3 "SI1922EDH-T1-GE3" SOT363-6N 897.24,2047.24 r0 top
QSFP "Pressfit" QSFP28_SINGLE_CAGE 1663.53,1661.46 r270 top
R1 "CRCW0402100KFKED" RESC1005X06A 2328.64,4075.46 r90 top value="100 k"
R3 "CRCW04022K00FKED" RESC1005X06A 2288.34,3963.8 r90 top value="2.0 k"
R4 "CRCW04022K00FKED" RESC1005X06A 2288.34,4075.46 r90 top value="2.0 k"
R5 "CRCW06030000Z0EA" RESC1608N 1721.39,2718.43 r90 top value=0
R6 "CRCW06030000Z0EA" RESC1608N 1792.04,2718.43 r90 top value=0
R12 "NoLoad" RESC1005X06A 1236.5,862.49 r180 top
R13 "CRCW0402200KFKED" RESC1005X06A 1112.49,635.26 r270 top value="200 k"
R14 "CRCW04024K75FKED" RESC1005X06A 921.26,807.09 r0 top value="4.75 k"
R15 "CRCW04024K75FKED" RESC1005X06A 921.26,748.03 r0 top value="4.75 k"
R16 "NoLoad" RESC1005X06A 1053.43,643.14 r0 top
R17 "NoLoad" RESC1005X06A 1053.43,603.77 r0 top
R18 "CRCW0402100KFKED" RESC1005X06A 2142.43,546.46 r90 top value="100 k"
R19 "CRCW06030000Z0EA" RESC1608N 5360.24,1417.32 r0 top value=0
R20 "NoLoad" RESC1005X06A 1236.5,822.27 r0 top
R21 "NoLoad" RESC1005X06A 1236.5,635.26 r0 top
R22 "NoLoad" RESC1005X06A 1236.5,595.89 r180 top
R23 "CRCW0402200KFKED" RESC1005X06A 1475.67,605.74 r270 top value="200 k"
R24 "CRCW0402100KFKED" RESC1005X06A 2088.57,546.46 r270 top value="100 k"
R25 "CRCW0402100KFKED" RESC1005X06A 1418.59,843.92 r0 top value="100 k"
R26 "NoLoad" RESC1005X06A 1418.59,615.58 r0 top
R27 "CRCW04020000Z0ED" RESC1005X06A 2556.62,421.26 r90 top value=0
R28 "CRCW04020000Z0ED" RESC1005X06A 3099.84,421.26 r90 top value=0
R29 "CRCW04020000Z0ED" RESC1005X06A 3712.6,480.32 r90 top value=0
R30 "CRCW04024K75FKED" RESC1005X06A 512.89,2320.54 r270 top value="4.75 k"
R31 "CRCW04024K75FKED" RESC1005X06A 512.89,2241.8 r90 top value="4.75 k"
R32 "CRCW0402100KFKED" RESC1005X06A 477.46,2182.74 r180 top value="100 k"
R33 "CRCW0402100KFKED" RESC1005X06A 402.66,2182.74 r0 top value="100 k"
R34 "CRCW06030000Z0EA" RESC1608N 5360.24,1259.84 r0 top value=0
R35 "CRCW06030000Z0EA" RESC1608N 5360.24,1102.36 r0 top value=0
R36 "CRCW06030000Z0EA" RESC1608N 5360.24,944.88 r0 top value=0
R37 "CRCW040210K0FKED" RESC1005X06A 806.69,2051.18 r90 top value="10.0 k"
R38 "CRCW0402200KFKED" RESC1005X06A 838.39,2145.87 r270 top value="200 k"
R39 "CRCW04024K75FKED" RESC1005X06A 1064.57,2397.64 r0 top value="4.75 k"
R40 "CRCW04024K75FKED" RESC1005X06A 1064.57,2351.71 r0 top value="4.75 k"
R41 "CRCW04024K75FKED" RESC1005X06A 1064.57,2305.77 r0 top value="4.75 k"
R42 "CRCW04024K75FKED" RESC1005X06A 729.92,2194.88 r180 top value="4.75 k"
R43 "CRCW04024K75FKED" RESC1005X06A 729.92,2336.61 r180 top value="4.75 k"
R44 "CRCW04024K75FKED" RESC1005X06A 1064.57,2259.84 r0 top value="4.75 k"
R45 "CRCW04024K75FKED" RESC1005X06A 1064.57,2213.91 r0 top value="4.75 k"
R46 "CRCW04024K75FKED" RESC1005X06A 729.92,2230.32 r180 top value="4.75 k"
R47 "CRCW04024K75FKED" RESC1005X06A 729.92,2301.18 r180 top value="4.75 k"
R48 "CRCW04024K75FKED" RESC1005X06A 1064.57,2167.98 r0 top value="4.75 k"
R49 "CRCW04024K75FKED" RESC1005X06A 1064.57,2122.05 r0 top value="4.75 k"
R75 "CRCW040210K0FKED" RESC1005X06A 379.47,3141.93 r180 top value="10.0 k"
R76 "CRCW04020000Z0ED" RESC1005X06A 379.17,3178.78 r180 top value=0
R77 "CRCW040273K2FKED" RESC1005X06A 585.76,3176.22 r0 top value=73.2k
R78 "CRCW040222K1FKEDC" RESC1005X06A 511.15,3212.61 r0 top value="22.1 k"
R79 "CRCW040210K0FKED" RESC1005X06A 434.15,3162.61 r90 top value="10.0 k"
R80 "CRCW04024K75FKED" RESC1005X06A 729.92,2266.78 r180 top value="4.75 k"
R81 "CRCW04024K75FKED" RESC1005X06A 729.92,2407.48 r180 top value="4.75 k"
R82 "CRCW04024K75FKED" RESC1005X06A 729.92,2372.05 r180 top value="4.75 k"
R500 "CRCW04025K10FKEDC" RESC1005X06A 5410.58,2953.94 r270 top value="5.1 k"
R501 "CRCW04025K10FKEDC" RESC1005X06A 5375.15,2953.94 r90 top value="5.1 k"
R502 "CRCW040212K0FKED" RESC1005X06A 5746.8,3282.68 r180 top value="12.0 k"
R503 "CRCW040210K0FKED" RESC1005X06A 5292.47,3203.94 r270 top value="10.0 k"
R504 "CRCW04020000Z0ED" RESC1005X06A 5593.65,2503.15 r0 top value=0
R505 "CRCW04020000Z0ED" RESC1005X06A 5593.65,2542.52 r0 top value=0
R506 "CRCW04020000Z0ED" RESC1005X06A 5593.65,2581.89 r0 top value=0
R507 "CRCW0402100KFKED" RESC1005X06A 5725.54,2869.3 r0 top value="100 k"
R508 "CRCW0402100KFKED" RESC1005X06A 5796.41,2869.3 r180 top value="100 k"
R509 "CRCW04022K00FKED" RESC1005X06A 5654.68,2869.3 r180 top value="2.0 k"
R510 "CRCW040210K0FKED" RESC1005X06A 5583.81,2869.3 r0 top value="10.0 k"
S1 "SW-PB" Switch-PCB-wMounts 3705.71,3662.4 r180 top
TP1 "FPGA_DXP" TP-PTH-25/45 2228.35,2090.55 r270 top
TP2 "FPGA_DXN" TP-PTH-25/45 2228.35,2011.81 r0 top
TP3 "+3.3V" TP-PTH-65/100 905.51,2539.37 r180 top
TP4 "VDCIN" TP-PTH-65/100 905.51,3169.29 r180 top
TP6 "+1.8V" TP-PTH-65/100 5511.81,1574.8 r90 top
TP8 "VCCO_64" TP-PTH-65/100 5511.81,1417.32 r90 top
TP9 "SMDAT_VIO" TP-SMD40 846.46,748.03 r90 top
TP12 "SMCLK_VIO" TP-SMD40 846.46,807.09 r180 top
TP13 "PERST_VIO" TP-SMD40 846.46,688.98 r270 top
TP15 "WAKE_VIO" TP-SMD40 846.46,629.92 r270 top
TP17 "VBATT" TP-PTH-25/45 2228.35,2169.29 r0 top
TP18 "VCCO_84" TP-PTH-65/100 5511.81,1259.84 r0 top
TP19 "+3.3V" TP-SMD40 288.48,2500 r0 top
TP20 "+12V_PCIE_C" TP-PTH-65/100 1732.73,620.68 r270 top
TP21 "FAULT" TP-SMD40 2141.72,627.39 r270 top
TP22 "VREF_64" TP-PTH-65/100 905.51,2854.33 r270 top
TP23 "VCCO_85" TP-PTH-65/100 5511.81,1102.36 r270 top
TP24 "XEM8305_PG" TP-PTH-65/100 905.51,2696.85 r270 top
TP25 "VCCO_86" TP-PTH-65/100 5511.81,944.88 r270 top
TP26 "DGND" TP-PTH-65/100 905.51,3011.81 r270 top
TP27 "DGND" TP-PTH-25/45 444.88,578.74 r0 top
TP28 "DGND" TP-PTH-25/45 5511.81,625.98 r270 top
TP29 "DGND" TP-PTH-25/45 453.7,3471.34 r270 top
TP30 "TESTPOINT-SMD20" TP-SMD20 4087.16,826.14 r0 top
TP31 "TESTPOINT-SMD20" TP-SMD20 4060.1,813.75 r0 top
TP32 "+3.3V_PG" TP-SMD40 508.96,2500 r270 top
U1 "REF3012AIDBZT" SOT23-95P240X110 1535.37,2728.43 r0 top
U2 "PCA9306DCUR" PCA9306DCU 1039.65,759.28 r270 top
U3 "SIT9120AI-2B3-XXE156.250000" SIT9120AX-XB 4299.27,708.19 r180 top
U4 "SN74AXC1T45DCK" DCK-R-PDSO-G6 1226.66,729.75 r180 top
U5 "AP22653AW6-7" AP2265XW6 2090.54,424.41 r90 top
U6 "PCA9306DCUR" PCA9306DCU 1402.84,729.75 r270 top
U7 "NVT2010BS" QFN-24 897.24,2303.15 r180 top
U8 "FIN1001M5X" SOT23-5 4071.91,708.19 r0 top
U10 "TPS54429ERSA" TPS54429E 518.67,3016.65 r270 top
U500 "SN74AXC1T45DBVR" SOT23-6 5520.82,3668.51 r0 top
U501 "FT232HQ" FT232HQ 5501.13,3294.49 r180 top
U502 "SN74AXC1T45DBVR" SOT23-6 5796.41,3668.51 r0 top
U503 "SN74AXC1T45DBVR" SOT23-6 5658.61,3668.51 r0 top
U504 "SN74AXC1T45DBVR" SOT23-6 5383.02,3668.51 r0 top
U505 "93LC56B-E/MS-CFG001" MSOP-MS8_N 5682.24,2959.85 r0 top
Y500 "ABM8-12.000MHZ-B2-T" ABM8 5772.79,3105.52 r0 top

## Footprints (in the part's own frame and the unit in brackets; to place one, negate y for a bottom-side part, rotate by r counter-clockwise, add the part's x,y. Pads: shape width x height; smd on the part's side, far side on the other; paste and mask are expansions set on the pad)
1267AY [mm]
  rrect0% 2.3x5.2 smd: 1(-3.1,0) 2(3.1,0)
  silkscreen extent -4.21,-4.21 4.2,4.2
0455580003 [mm]
  round 3 hole 3 unplated: 0(-4.2,7.3) 0(4.2,7.3)
  round 3 hole 1.8: 1(-4.2,0) 2(0,0) 3(4.2,0) 4(-4.2,-4.2) 5(0,-4.2) 6(4.2,-4.2)
  silkscreen extent -7,1 7,11.58
ABM8 [mm]
  rect 1.3x1.05 smd: 1(-1.15,-0.925) 2(1.15,-0.925) 3(1.15,0.925) 4(-1.15,0.925)
  silkscreen extent -1.98,-1.42 1.98,0.8
AP2265XW6 [mm]
  rect 0.9x0.7 smd: 1(-1.25,0.95) 2(-1.25,0) 3(-1.25,-0.95) 4(1.25,-0.95) 5(1.25,0) 6(1.25,0.95)
  silkscreen extent -1.9,-1.55 0.85,1.55
CAPAE9083X70N [mm] "Aluminum Electrolytic Capacitor, Body 8.30x8.30x7.00mm, IPC Medium Density"
  rect 3.6x1.65 smd: 1(-3.325,0) 2(3.325,0)
  silkscreen extent -4.25,-4.25 4.25,4.25
CAPC1005X06A [mm] "Chip Capacitor, 2-Leads, Body 1.00x0.50mm, OK custom footprint"
  rect 0.52x0.55 smd: 1(-0.51,0) 2(0.51,0)
  body extent -0.5,-0.25 0.5,0.25, height 0.5
CAPC3216N [mm] "Chip Capacitor, Body 3.2x1.6mm, IPC Medium Density"
  rect 1.3x1.8 smd: 1(-1.45,0) 2(1.45,0)
  silkscreen extent -1.2,-1.08 1.2,1.08, body extent -1.6,-0.85 1.6,0.85, height 1.72
CD1608-0603-PIN1-CATHODE [mm] "Chip Diode; Body 1.6 x 0.8 mm (LxW typ)"
  rect 1.1x1 smd: 1(-0.85,0) 2(0.85,0)
  silkscreen extent -1.58,-0.68 0.6,0.68
CIGT252010 [mm]
  rect 0.8x2 smd: 1(-1,0) 2(1,0)
CUI-PJ102A [mm] "2.1mm/5.5mm DC power jack"
  round 2.25 hole 1.5: 1(0,13.7) 2(0,7.7) 3(4.7,10.7)
  silkscreen extent -4.5,2.58 4.5,14.5
D5V0FS4U10LP [mm]
  rect 0.25x0.625 smd mask+0.038: 1(-1,-0.387) 2(-0.5,-0.387) 4(0.5,-0.387) 5(1,-0.387) 6(1,0.387) 7(0.5,0.387) 9(-0.5,0.387) 10(-1,0.387)
  rect 0.45x0.7 smd mask+0.025: 3(0,-0.35)
  rect 0.45x0.575 smd mask+0.025: 8(0,0.413)
  silkscreen extent -1.35,-0.9 1.35,0.55
DCK-R-PDSO-G6 [mm]
  rect 0.35x0.85 smd: 1(-0.65,-1.1) 2(0,-1.1) 3(0.65,-1.1) 4(0.65,1.1) 5(0,1.1) 6(-0.65,1.1)
  silkscreen extent -1.01,-1.55 1.01,0.65
DO-214AA [mm]
  rect 2.5x2.3 smd: 1(-2.15,0) 2(2.15,0)
  silkscreen extent -2.35,-2.04 2.35,2.04
ERF6-40-03.5-L-DV-A-K-TR [mm]
  rect 0.35x1 smd: 1(12.383,-0.8) 2(12.383,0.8) 3(11.748,-0.8) 4(11.748,0.8) 5(11.113,-0.8) 6(11.113,0.8) 7(10.478,-0.8) 8(10.478,0.8) 9(9.843,-0.8) 10(9.843,0.8) 11(9.208,-0.8) 12(9.208,0.8) 13(8.573,-0.8) 14(8.573,0.8) 15(7.938,-0.8) 16(7.938,0.8) 17(7.303,-0.8) 18(7.303,0.8) 19(6.668,-0.8) 20(6.668,0.8) 21(6.033,-0.8) 22(6.033,0.8) 23(5.398,-0.8) 24(5.398,0.8) 25(4.763,-0.8) 26(4.763,0.8) 27(4.128,-0.8) 28(4.128,0.8) 29(3.493,-0.8) 30(3.493,0.8) 31(2.858,-0.8) 32(2.858,0.8) 33(2.223,-0.8) 34(2.223,0.8) 35(1.588,-0.8) 36(1.588,0.8) 37(0.953,-0.8) 38(0.953,0.8) 39(0.318,-0.8) 40(0.318,0.8) 41(-0.317,-0.8) 42(-0.317,0.8) 43(-0.952,-0.8) 44(-0.952,0.8) 45(-1.587,-0.8) 46(-1.587,0.8) 47(-2.222,-0.8) 48(-2.222,0.8) 49(-2.857,-0.8) 50(-2.857,0.8) 51(-3.492,-0.8) 52(-3.492,0.8) 53(-4.127,-0.8) 54(-4.127,0.8) 55(-4.762,-0.8) 56(-4.762,0.8) 57(-5.397,-0.8) 58(-5.397,0.8) 59(-6.032,-0.8) 60(-6.032,0.8) 61(-6.667,-0.8) 62(-6.667,0.8) 63(-7.302,-0.8) 64(-7.302,0.8) 65(-7.937,-0.8) 66(-7.937,0.8) 67(-8.572,-0.8) 68(-8.572,0.8) 69(-9.207,-0.8) 70(-9.207,0.8) 71(-9.842,-0.8) 72(-9.842,0.8) 73(-10.477,-0.8) 74(-10.477,0.8) 75(-11.112,-0.8) 76(-11.112,0.8) 77(-11.747,-0.8) 78(-11.747,0.8) 79(-12.382,-0.8) 80(-12.382,0.8)
  round 0.95 hole 0.95 unplated: ""(-13.785,0.47) ""(13.785,0)
  silkscreen extent -15.06,-1.9 15.06,1.25, body extent -15.06,-1.5 15.06,1.5, height 3.7
ERF6-50-03.5-L-DV-A-K-TR [mm]
  rect 0.35x1 smd: 1(15.558,-0.8) 2(15.558,0.8) 3(14.923,-0.8) 4(14.923,0.8) 5(14.288,-0.8) 6(14.288,0.8) 7(13.653,-0.8) 8(13.653,0.8) 9(13.018,-0.8) 10(13.018,0.8) 11(12.383,-0.8) 12(12.383,0.8) 13(11.748,-0.8) 14(11.748,0.8) 15(11.113,-0.8) 16(11.113,0.8) 17(10.478,-0.8) 18(10.478,0.8) 19(9.843,-0.8) 20(9.843,0.8) 21(9.208,-0.8) 22(9.208,0.8) 23(8.573,-0.8) 24(8.573,0.8) 25(7.938,-0.8) 26(7.938,0.8) 27(7.303,-0.8) 28(7.303,0.8) 29(6.668,-0.8) 30(6.668,0.8) 31(6.033,-0.8) 32(6.033,0.8) 33(5.398,-0.8) 34(5.398,0.8) 35(4.763,-0.8) 36(4.763,0.8) 37(4.128,-0.8) 38(4.128,0.8) 39(3.493,-0.8) 40(3.493,0.8) 41(2.858,-0.8) 42(2.858,0.8) 43(2.223,-0.8) 44(2.223,0.8) 45(1.588,-0.8) 46(1.588,0.8) 47(0.953,-0.8) 48(0.953,0.8) 49(0.318,-0.8) 50(0.318,0.8) 51(-0.317,-0.8) 52(-0.317,0.8) 53(-0.952,-0.8) 54(-0.952,0.8) 55(-1.587,-0.8) 56(-1.587,0.8) 57(-2.222,-0.8) 58(-2.222,0.8) 59(-2.857,-0.8) 60(-2.857,0.8) 61(-3.492,-0.8) 62(-3.492,0.8) 63(-4.127,-0.8) 64(-4.127,0.8) 65(-4.762,-0.8) 66(-4.762,0.8) 67(-5.397,-0.8) 68(-5.397,0.8) 69(-6.032,-0.8) 70(-6.032,0.8) 71(-6.667,-0.8) 72(-6.667,0.8) 73(-7.302,-0.8) 74(-7.302,0.8) 75(-7.937,-0.8) 76(-7.937,0.8) 77(-8.572,-0.8) 78(-8.572,0.8) 79(-9.207,-0.8) 80(-9.207,0.8) 81(-9.842,-0.8) 82(-9.842,0.8) 83(-10.477,-0.8) 84(-10.477,0.8) 85(-11.112,-0.8) 86(-11.112,0.8) 87(-11.747,-0.8) 88(-11.747,0.8) 89(-12.382,-0.8) 90(-12.382,0.8) 91(-13.017,-0.8) 92(-13.017,0.8) 93(-13.652,-0.8) 94(-13.652,0.8) 95(-14.287,-0.8) 96(-14.287,0.8) 97(-14.922,-0.8) 98(-14.922,0.8) 99(-15.557,-0.8) 100(-15.557,0.8)
  round 0.95 hole 0.95 unplated: ""(-16.96,0.47) ""(16.96,0)
  silkscreen extent -18.23,-1.9 18.24,1.25, body extent -18.24,-1.5 18.24,1.5, height 3.7
FID1MM/2MM-SS [mm] "Fiducial 1mm copper, 2mm soldermask, single-side"
  round 1 smd paste-0.5 mask+0.5: FID?(0,0)
FT232HQ [mm]
  rrect100% 0.8x0.25 smd: 1(-4.025,2.75) 2(-4.025,2.25) 3(-4.025,1.75) 4(-4.025,1.25) 5(-4.025,0.75) 6(-4.025,0.25) 7(-4.025,-0.25) 8(-4.025,-0.75) 9(-4.025,-1.25) 10(-4.025,-1.75) 11(-4.025,-2.25) 12(-4.025,-2.75) 25(4.025,-2.75) 26(4.025,-2.25) 27(4.025,-1.75) 28(4.025,-1.25) 29(4.025,-0.75) 30(4.025,-0.25) 31(4.025,0.25) 32(4.025,0.75) 33(4.025,1.25) 34(4.025,1.75) 35(4.025,2.25) 36(4.025,2.75)
  rrect100% 0.25x0.8 smd: 13(-2.75,-4.025) 14(-2.25,-4.025) 15(-1.75,-4.025) 16(-1.25,-4.025) 17(-0.75,-4.025) 18(-0.25,-4.025) 19(0.25,-4.025) 20(0.75,-4.025) 21(1.25,-4.025) 22(1.75,-4.025) 23(2.25,-4.025) 24(2.75,-4.025) 37(2.75,4.025) 38(2.25,4.025) 39(1.75,4.025) 40(1.25,4.025) 41(0.75,4.025) 42(0.25,4.025) 43(-0.25,4.025) 44(-0.75,4.025) 45(-1.25,4.025) 46(-1.75,4.025) 47(-2.25,4.025) 48(-2.75,4.025)
  rect 6.29x6.29 smd paste-10: PAD(0,0)
  silkscreen extent -4.51,-4.06 4.06,4.51
HDR1X20-2MM [mm] "2mm 1x20 Header"
  rect 1.3x1.3 hole 0.8: 1(-19,0)
  round 1.3 hole 0.8: 2(-17,0) 3(-15,0) 4(-13,0) 5(-11,0) 6(-9,0) 7(-7,0) 8(-5,0) 9(-3,0) 10(-1,0) 11(1,0) 12(3,0) 13(5,0) 14(7,0) 15(9,0) 16(11,0) 17(13,0) 18(15,0) 19(17,0) 20(19,0)
  silkscreen extent -20,-1 20,1
HDR2X4 [mil] "0.1\" 2x4 header"
  rect 65x65 hole 40: 1(0,0)
  round 65 hole 40: 2(0,100) 3(100,0) 4(100,100) 5(200,0) 6(200,100) 7(300,0) 8(300,100)
  silkscreen extent -50,-50 350,150
HDR2X20-2MM [mm] "2mm 2x20 header"
  rect 1.3x1.3 hole 0.8: 1(-19,-1)
  round 1.3 hole 0.8: 2(-19,1) 3(-17,-1) 4(-17,1) 5(-15,-1) 6(-15,1) 7(-13,-1) 8(-13,1) 9(-11,-1) 10(-11,1) 11(-9,-1) 12(-9,1) 13(-7,-1) 14(-7,1) 15(-5,-1) 16(-5,1) 17(-3,-1) 18(-3,1) 19(-1,-1) 20(-1,1) 21(1,-1) 22(1,1) 23(3,-1) 24(3,1) 25(5,-1) 26(5,1) 27(7,-1) 28(7,1) 29(9,-1) 30(9,1) 31(11,-1) 32(11,1) 33(13,-1) 34(13,1) 35(15,-1) 36(15,1) 37(17,-1) 38(17,1) 39(19,-1) 40(19,1)
  silkscreen extent -20,-2 20,2
INDC1608X06N [mm] "Chip Inductor, 2-Leads, Body 1.60x0.80mm, IPC Medium Density"
  rect 0.65x0.98 smd: 1(-0.78,0) 2(0.78,0)
  silkscreen extent -0.25,-0.69 0.25,0.69, body extent -0.88,-0.48 0.87,0.47, height 0.6
MOLEX-0022232021 [mil]
  rect 65x65 hole 40.16: 1(-50,0)
  round 65 hole 40.16: 2(50,0)
  silkscreen extent -103,-125 103,131, body extent -100,-122 100,128, height 422
MouseBite-01 [mil]
  round 78.74 hole 78.74 unplated mask+1: 0(-105,39.37) 0(105,39.37)
  round 30 hole 30 unplated mask+1: 0(-80,0) 0(80,0)
  round 20 hole 20 unplated mask+1: 0(-40,-5) 0(0,-5) 0(40,-5)
MSOP-MS8_N [mm] "TSOP, 8-Leads, Body 3x3mm, Pitch 0.65mm, IPC Medium Density"
  rect 1.45x0.45 smd mask+0.051: 1(-2.2,0.975) 2(-2.2,0.325) 3(-2.2,-0.325) 4(-2.2,-0.975) 5(2.2,-0.975) 6(2.2,-0.325) 7(2.2,0.325) 8(2.2,0.975)
  silkscreen extent -2.92,-1.57 1.52,1.57, body extent -1.55,-1.55 1.55,1.55, height 1.1
MTG-3.2/6.5-PTH [mm] "Mounting hole, 3.2mm ID, 6.5mm OD, plated"
  round 6.5 hole 3.2: 1(0,0)
okLogo-23x5-2021 [mil] "Opal Kelly silkscreen logo (23mm x 5mm) - 2021 update"
  silkscreen extent -4,-15 672,100
PCA9306DCU [mm]
  rect 0.75x0.25 smd: 1(-1.55,0.75) 2(-1.55,0.25) 3(-1.55,-0.25) 4(-1.55,-0.75) 5(1.55,-0.75) 6(1.55,-0.25) 7(1.55,0.25) 8(1.55,0.75)
  silkscreen extent -2.03,-1.09 1.02,1.09
PCIEx8-FULL-HEIGHT [mm] "PCI Express 8-lane edge connector, full height"
  rect 0.7x3.2 smd far side paste-10: A1(-11.5,4)
  rect 0.7x4.2 smd far side paste-10: A2(-10.5,3.5) A3(-9.5,3.5) A4(-8.5,3.5) A5(-7.5,3.5) A6(-6.5,3.5) A7(-5.5,3.5) A8(-4.5,3.5) A9(-3.5,3.5) A10(-2.5,3.5) A11(-1.5,3.5) A12(1.5,3.5) A13(2.5,3.5) A14(3.5,3.5) A15(4.5,3.5) A16(5.5,3.5) A17(6.5,3.5) A18(7.5,3.5) A19(8.5,3.5) A20(9.5,3.5) A21(10.5,3.5) A22(11.5,3.5) A23(12.5,3.5) A24(13.5,3.5) A25(14.5,3.5) A26(15.5,3.5) A27(16.5,3.5) A28(17.5,3.5) A29(18.5,3.5) A30(19.5,3.5) A31(20.5,3.5) A32(21.5,3.5) A33(22.5,3.5) A34(23.5,3.5) A35(24.5,3.5) A36(25.5,3.5) A37(26.5,3.5) A38(27.5,3.5) A39(28.5,3.5) A40(29.5,3.5) A41(30.5,3.5) A42(31.5,3.5) A43(32.5,3.5) A44(33.5,3.5) A45(34.5,3.5) A46(35.5,3.5) A47(36.5,3.5) A48(37.5,3.5) A49(38.5,3.5)
  rect 0.7x4.2 smd paste-10: B1(-11.5,3.5) B2(-10.5,3.5) B3(-9.5,3.5) B4(-8.5,3.5) B5(-7.5,3.5) B6(-6.5,3.5) B7(-5.5,3.5) B8(-4.5,3.5) B9(-3.5,3.5) B10(-2.5,3.5) B11(-1.5,3.5) B12(1.5,3.5) B13(2.5,3.5) B14(3.5,3.5) B15(4.5,3.5) B16(5.5,3.5) B18(7.5,3.5) B19(8.5,3.5) B20(9.5,3.5) B21(10.5,3.5) B22(11.5,3.5) B23(12.5,3.5) B24(13.5,3.5) B25(14.5,3.5) B26(15.5,3.5) B27(16.5,3.5) B28(17.5,3.5) B29(18.5,3.5) B30(19.5,3.5) B32(21.5,3.5) B33(22.5,3.5) B34(23.5,3.5) B35(24.5,3.5) B36(25.5,3.5) B37(26.5,3.5) B38(27.5,3.5) B39(28.5,3.5) B40(29.5,3.5) B41(30.5,3.5) B42(31.5,3.5) B43(32.5,3.5) B44(33.5,3.5) B45(34.5,3.5) B46(35.5,3.5) B47(36.5,3.5) B49(38.5,3.5)
  rect 0.7x3.2 smd paste-10: B17(6.5,4) B31(20.5,4) B48(37.5,4)
  L1-Top keep-out region: -57.15,89.7 -44.45,89.7 -44.45,110.15 -57.15,110.15
  L1-Top keep-out region: -57.15,110.15 80,110.15 80,111.15 -57.15,111.15
  L1-Top keep-out region: 80,108.15 105.42,108.15 105.42,111.15 80,111.15
  L1-Top keep-out region: 105.42,13.75 110.5,13.75 110.5,111.15 105.42,111.15
  L1-Top keep-out region: 39.15,12.75 110.5,12.75 110.5,13.75 39.15,13.75
  L1-Top keep-out region: -57.15,4.45 -42.15,4.45 -42.131,4.453 -42.114,4.464 -42.103,4.481 -42.1,4.5 -42.1,4.5 -42.1,12.7 -23.85,12.7 -23.85,7.95 -23.847,7.931 -23.836,7.914 -23.819,7.903 -23.8,7.9 -23.8,7.9 -15.8,7.9 -15.781,7.903 -15.764,7.914 -15.753,7.931 -15.75,7.95 -15.75,7.95 -15.75,7.95 -15.75,7.951 -15.75,7.951 -15.75,10.925 -15.574,11.695 -15.081,12.312 -14.37,12.655 -13.58,12.655 -12.869,12.312 -12.376,11.695 -12.2,10.925 -12.2,10.925 -12.195,10.903 -12.181,10.886 -12.161,10.876 -12.139,10.876 -12.119,10.886 -12.105,10.903 -12.1,10.925 -12.1,10.925 -12.1,13.75 -12.103,13.769 -12.114,13.786 -12.131,13.797 -12.15,13.8 -12.15,13.8 -57.15,13.8 -57.169,13.797 -57.186,13.786 -57.197,13.769 -57.2,13.75 -57.2,13.75 -57.2,4.5 -57.197,4.481 -57.186,4.464 -57.169,4.453 -57.15,4.45
  L4-BOT keep-out region: 39.15,12.75 110.5,12.75 110.5,13.75 39.15,13.75
  L4-BOT keep-out region: 105.42,13.75 110.5,13.75 110.5,111.15 105.42,111.15
  L4-BOT keep-out region: 80,108.15 105.42,108.15 105.42,111.15 80,111.15
  L4-BOT keep-out region: -57.15,110.15 80,110.15 80,111.15 -57.15,111.15
  L4-BOT keep-out region: -57.15,89.7 -44.45,89.7 -44.45,110.15 -57.15,110.15
  L4-BOT keep-out region: -57.15,13.75 -52.07,13.75 -52.07,89.7 -57.15,89.7
  L4-BOT keep-out region: -57.15,4.45 -42.15,4.45 -42.131,4.453 -42.114,4.464 -42.103,4.481 -42.1,4.5 -42.1,4.5 -42.1,12.7 -23.85,12.7 -23.85,7.95 -23.847,7.931 -23.836,7.914 -23.819,7.903 -23.8,7.9 -23.8,7.9 -15.8,7.9 -15.781,7.903 -15.764,7.914 -15.753,7.931 -15.75,7.95 -15.75,7.95 -15.75,7.95 -15.75,7.951 -15.75,7.951 -15.75,10.925 -15.574,11.695 -15.081,12.312 -14.37,12.655 -13.58,12.655 -12.869,12.312 -12.376,11.695 -12.2,10.925 -12.2,10.925 -12.195,10.903 -12.181,10.886 -12.161,10.876 -12.139,10.876 -12.119,10.886 -12.105,10.903 -12.1,10.925 -12.1,10.925 -12.1,13.75 -12.103,13.769 -12.114,13.786 -12.131,13.797 -12.15,13.8 -12.15,13.8 -57.15,13.8 -57.169,13.797 -57.186,13.786 -57.197,13.769 -57.2,13.75 -57.2,13.75 -57.2,4.5 -57.197,4.481 -57.186,4.464 -57.169,4.453 -57.15,4.45
  Keep-Out Layer region: -23.8,4.5 -15.8,4.5 -15.8,7.95 -23.8,7.95
QFN-24 [mm] "QFN, 24-Leads, Body 4x4mm, Pitch 0.5mm"
  rect 2.1x2.1 smd paste-1.2: 0(0,0)
  rect 0.9x0.24 smd: 1(-2.05,1.25) 2(-2.05,0.75) 3(-2.05,0.25) 4(-2.05,-0.25) 5(-2.05,-0.75) 6(-2.05,-1.25) 13(2.05,-1.25) 14(2.05,-0.75) 15(2.05,-0.25) 16(2.05,0.25) 17(2.05,0.75) 18(2.05,1.25)
  rect 0.24x0.9 smd: 7(-1.25,-2.05) 8(-0.75,-2.05) 9(-0.25,-2.05) 10(0.25,-2.05) 11(0.75,-2.05) 12(1.25,-2.05) 19(1.25,2.05) 20(0.75,2.05) 21(0.25,2.05) 22(-0.25,2.05) 23(-0.75,2.05) 24(-1.25,2.05)
  silkscreen extent -2.69,-2.17 2.17,2.69, body extent -2.07,-2.07 2.07,2.07, height 0.8
QSFP28_RECEPTACLE_SFF-8679 [mm]
  rect 0.35x1.8 smd: 1(1.4,7.37) 2(2.2,7.37) 3(3,7.37) 4(3.8,7.37) 5(4.6,7.37) 6(5.4,7.37) 7(6.2,7.37) 8(7,7.37) 9(7.8,7.37) 10(8.6,7.37) 11(9.4,7.37) 12(10.2,7.37) 13(11,7.37) 14(11.8,7.37) 15(12.6,7.37) 16(13.4,7.37) 17(14.2,7.37) 18(15,7.37) 19(15.8,7.37) 20(15.4,9.88) 21(14.6,9.88) 22(13.8,9.88) 23(13,9.88) 24(12.2,9.88) 25(11.4,9.88) 26(10.6,9.88) 27(9.8,9.88) 28(9,9.88) 29(8.2,9.88) 30(7.4,9.88) 31(6.6,9.88) 32(5.8,9.88) 33(5,9.88) 34(4.2,9.88) 35(3.4,9.88) 36(2.6,9.88) 37(1.8,9.88) 38(1,9.88)
  round 1.55 hole 1.55 unplated: MH(0,0) MH(16.8,0)
  L1-Top keep-out region: -0.5,-3.16 0.5,-3.16 0.5,-2.16 -0.5,-2.16
  L1-Top keep-out region: 16.3,-3.16 17.3,-3.16 17.3,-2.16 16.3,-2.16
  silkscreen extent -0.8,-3 17.6,9.7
